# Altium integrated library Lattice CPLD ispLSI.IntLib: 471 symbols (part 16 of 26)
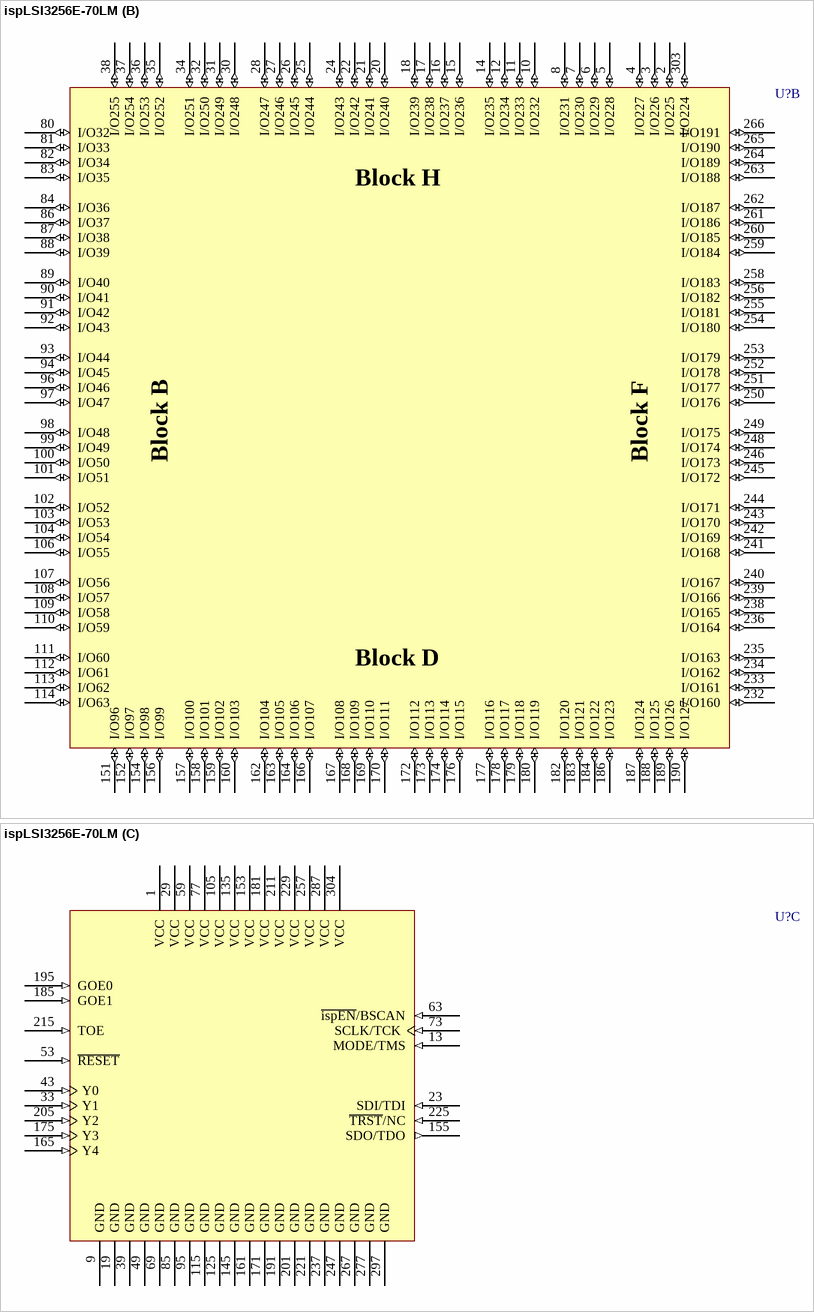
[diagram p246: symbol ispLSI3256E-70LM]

## ispLSI3256E-70LM
designator U?
In-System Programmable High-Density PLD
footprint MQFP304_N (Shrink QFP, 304-Leads, Body 40x40mm, Pitch 0.5mm, IPC Medium Density)
footprint MQFP304_L (Shrink QFP, 304-Leads, Body 40x40mm, Pitch 0.5mm, IPC High Density)
footprint MQFP304_M (Shrink QFP, 304-Leads, Body 40x40mm, Pitch 0.5mm, IPC Low Density)
3D model 3256E-MQFP304 (304-Pin Shrink Quad Flat Pack 0.5 mm Pitch)
part A pins: 40 I/O0 (io), 41 I/O1 (io), 42 I/O2 (io), 44 I/O3 (io), 45 I/O4 (io), 46 I/O5 (io), 47 I/O6 (io), 48 I/O7 (io), 50 I/O8 (io), 51 I/O9 (io), 52 I/O10 (io), 54 I/O11 (io), 55 I/O12 (io), 56 I/O13 (io), 57 I/O14 (io), 58 I/O15 (io), 60 I/O16 (io), 61 I/O17 (io), 62 I/O18 (io), 64 I/O19 (io), 65 I/O20 (io), 66 I/O21 (io), 67 I/O22 (io), 68 I/O23 (io), 70 I/O24 (io), 71 I/O25 (io), 72 I/O26 (io), 74 I/O27 (io), 75 I/O28 (io), 76 I/O29 (io), 78 I/O30 (io), 79 I/O31 (io), 116 I/O64 (io), 117 I/O65 (io), 118 I/O66 (io), 119 I/O67 (io), 120 I/O68 (io), 121 I/O69 (io), 122 I/O70 (io), 123 I/O71 (io), 124 I/O72 (io), 126 I/O73 (io), 127 I/O74 (io), 128 I/O75 (io), 129 I/O76 (io), 130 I/O77 (io), 131 I/O78 (io), 132 I/O79 (io), 133 I/O80 (io), 134 I/O81 (io), 136 I/O82 (io), 137 I/O83 (io), 138 I/O84 (io), 139 I/O85 (io), 140 I/O86 (io), 141 I/O87 (io), 142 I/O88 (io), 143 I/O89 (io), 144 I/O90 (io), 146 I/O91 (io), 147 I/O92 (io), 148 I/O93 (io), 149 I/O94 (io), 150 I/O95 (io), 192 I/O128 (io), 193 I/O129 (io), 194 I/O130 (io), 196 I/O131 (io), 197 I/O132 (io), 198 I/O133 (io), 199 I/O134 (io), 200 I/O135 (io), 202 I/O136 (io), 203 I/O137 (io), 204 I/O138 (io), 206 I/O139 (io), 207 I/O140 (io), 208 I/O141 (io), 209 I/O142 (io), 210 I/O143 (io), 212 I/O144 (io), 213 I/O145 (io), 214 I/O146 (io), 216 I/O147 (io), 217 I/O148 (io), 218 I/O149 (io), 219 I/O150 (io), 220 I/O151 (io), 222 I/O152 (io), 223 I/O153 (io), 224 I/O154 (io), 226 I/O155 (io), 227 I/O156 (io), 228 I/O157 (io), 230 I/O158 (io), 231 I/O159 (io), 268 I/O192 (io), 269 I/O193 (io), 270 I/O194 (io), 271 I/O195 (io), 272 I/O196 (io), 273 I/O197 (io), 274 I/O198 (io), 275 I/O199 (io), 276 I/O200 (io), 278 I/O201 (io), 279 I/O202 (io), 280 I/O203 (io), 281 I/O204 (io), 282 I/O205 (io), 283 I/O206 (io), 284 I/O207 (io), 285 I/O208 (io), 286 I/O209 (io), 288 I/O210 (io), 289 I/O211 (io), 290 I/O212 (io), 291 I/O213 (io), 292 I/O214 (io), 293 I/O215 (io), 294 I/O216 (io), 295 I/O217 (io), 296 I/O218 (io), 298 I/O219 (io), 299 I/O220 (io), 300 I/O221 (io), 301 I/O222 (io), 302 I/O223 (io)
part B pins: 2 I/O225 (io), 3 I/O226 (io), 4 I/O227 (io), 5 I/O228 (io), 6 I/O229 (io), 7 I/O230 (io), 8 I/O231 (io), 10 I/O232 (io), 11 I/O233 (io), 12 I/O234 (io), 14 I/O235 (io), 15 I/O236 (io), 16 I/O237 (io), 17 I/O238 (io), 18 I/O239 (io), 20 I/O240 (io), 21 I/O241 (io), 22 I/O242 (io), 24 I/O243 (io), 25 I/O244 (io), 26 I/O245 (io), 27 I/O246 (io), 28 I/O247 (io), 30 I/O248 (io), 31 I/O249 (io), 32 I/O250 (io), 34 I/O251 (io), 35 I/O252 (io), 36 I/O253 (io), 37 I/O254 (io), 38 I/O255 (io), 80 I/O32 (io), 81 I/O33 (io), 82 I/O34 (io), 83 I/O35 (io), 84 I/O36 (io), 86 I/O37 (io), 87 I/O38 (io), 88 I/O39 (io), 89 I/O40 (io), 90 I/O41 (io), 91 I/O42 (io), 92 I/O43 (io), 93 I/O44 (io), 94 I/O45 (io), 96 I/O46 (io), 97 I/O47 (io), 98 I/O48 (io), 99 I/O49 (io), 100 I/O50 (io), 101 I/O51 (io), 102 I/O52 (io), 103 I/O53 (io), 104 I/O54 (io), 106 I/O55 (io), 107 I/O56 (io), 108 I/O57 (io), 109 I/O58 (io), 110 I/O59 (io), 111 I/O60 (io), 112 I/O61 (io), 113 I/O62 (io), 114 I/O63 (io), 151 I/O96 (io), 152 I/O97 (io), 154 I/O98 (io), 156 I/O99 (io), 157 I/O100 (io), 158 I/O101 (io), 159 I/O102 (io), 160 I/O103 (io), 162 I/O104 (io), 163 I/O105 (io), 164 I/O106 (io), 166 I/O107 (io), 167 I/O108 (io), 168 I/O109 (io), 169 I/O110 (io), 170 I/O111 (io), 172 I/O112 (io), 173 I/O113 (io), 174 I/O114 (io), 176 I/O115 (io), 177 I/O116 (io), 178 I/O117 (io), 179 I/O118 (io), 180 I/O119 (io), 182 I/O120 (io), 183 I/O121 (io), 184 I/O122 (io), 186 I/O123 (io), 187 I/O124 (io), 188 I/O125 (io), 189 I/O126 (io), 190 I/O127 (io), 232 I/O160 (io), 233 I/O161 (io), 234 I/O162 (io), 235 I/O163 (io), 236 I/O164 (io), 238 I/O165 (io), 239 I/O166 (io), 240 I/O167 (io), 241 I/O168 (io), 242 I/O169 (io), 243 I/O170 (io), 244 I/O171 (io), 245 I/O172 (io), 246 I/O173 (io), 248 I/O174 (io), 249 I/O175 (io), 250 I/O176 (io), 251 I/O177 (io), 252 I/O178 (io), 253 I/O179 (io), 254 I/O180 (io), 255 I/O181 (io), 256 I/O182 (io), 258 I/O183 (io), 259 I/O184 (io), 260 I/O185 (io), 261 I/O186 (io), 262 I/O187 (io), 263 I/O188 (io), 264 I/O189 (io), 265 I/O190 (io), 266 I/O191 (io), 303 I/O224 (io)
part C pins: 1 VCC (power), 9 GND (power), 13 MODE/TMS (in), 19 GND (power), 23 SDI/TDI (in), 29 VCC (power), 33 Y1 (in), 39 GND (power), 43 Y0 (in), 49 GND (power), 53 ~{RESET} (in), 59 VCC (power), 63 ~{ispEN}/BSCAN (in), 69 GND (power), 73 SCLK/TCK (in), 77 VCC (power), 85 GND (power), 95 GND (power), 105 VCC (power), 115 GND (power), 125 GND (power), 135 VCC (power), 145 GND (power), 153 VCC (power), 155 SDO/TDO (out), 161 GND (power), 165 Y4 (in), 171 GND (power), 175 Y3 (in), 181 VCC (power), 185 GOE1 (in), 191 GND (power), 195 GOE0 (in), 201 GND (power), 205 Y2 (in), 211 VCC (power), 215 TOE (in), 221 GND (power), 225 ~{TRST}/NC (in), 229 VCC (power), 237 GND (power), 247 GND (power), 257 VCC (power), 267 GND (power), 277 GND (power), 287 VCC (power), 297 GND (power), 304 VCC (power)

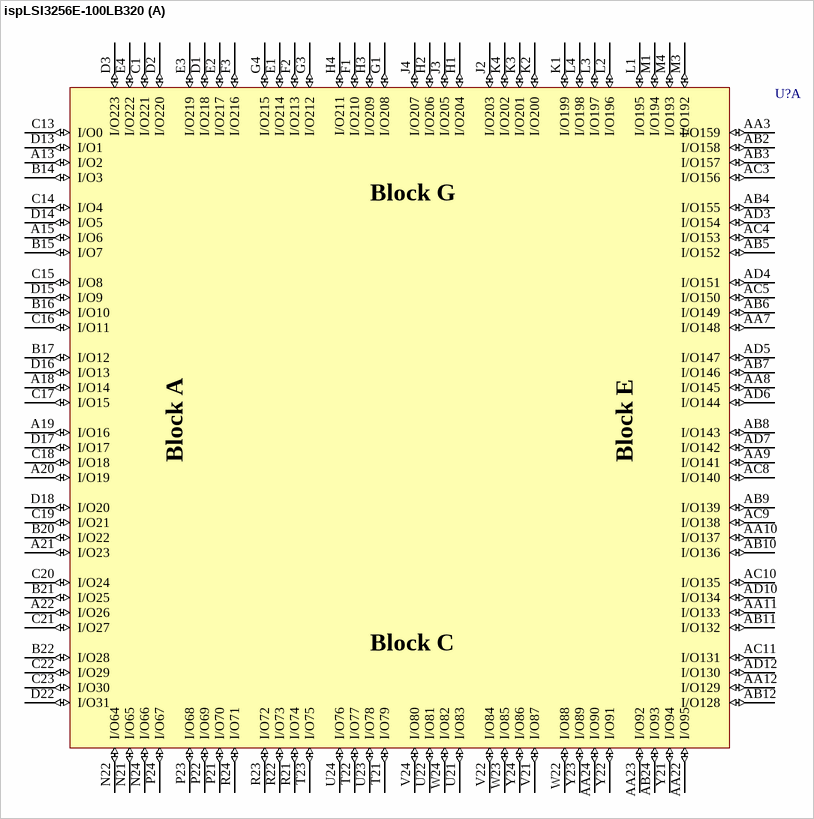
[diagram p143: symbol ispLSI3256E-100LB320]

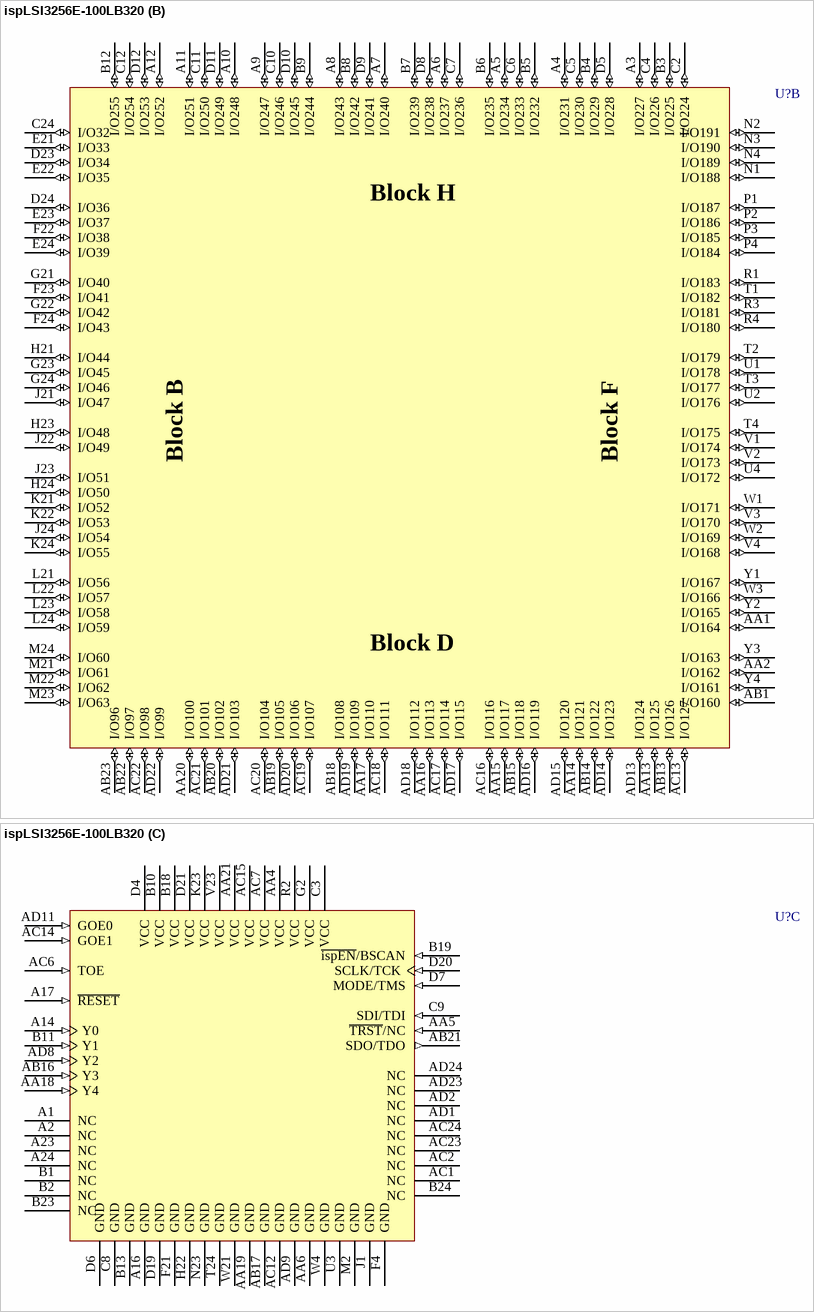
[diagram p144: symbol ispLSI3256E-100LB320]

## ispLSI3256E-100LB320
designator U?
In-System Programmable High-Density PLD
footprint SBGA320 (BGA, 320-Leads, Body 31x31mm, Pitch 1.27mm)
3D model 3256E-SBGA320 (320-Ball Super Ball Grid Array (SBGA320))
part A pins: A13 I/O2 (io), A15 I/O6 (io), A18 I/O14 (io), A19 I/O16 (io), A20 I/O19 (io), A21 I/O23 (io), A22 I/O26 (io), AA3 I/O159 (io), AA7 I/O148 (io), AA8 I/O145 (io), AA9 I/O141 (io), AA10 I/O137 (io), AA11 I/O133 (io), AA12 I/O129 (io), AA22 I/O95 (io), AA23 I/O92 (io), AA24 I/O90 (io), AB2 I/O158 (io), AB3 I/O157 (io), AB4 I/O155 (io), AB5 I/O152 (io), AB6 I/O149 (io), AB7 I/O146 (io), AB8 I/O143 (io), AB9 I/O139 (io), AB10 I/O136 (io), AB11 I/O132 (io), AB12 I/O128 (io), AB24 I/O93 (io), AC3 I/O156 (io), AC4 I/O153 (io), AC5 I/O150 (io), AC8 I/O140 (io), AC9 I/O138 (io), AC10 I/O135 (io), AC11 I/O131 (io), AD3 I/O154 (io), AD4 I/O151 (io), AD5 I/O147 (io), AD6 I/O144 (io), AD7 I/O142 (io), AD10 I/O134 (io), AD12 I/O130 (io), B14 I/O3 (io), B15 I/O7 (io), B16 I/O10 (io), B17 I/O12 (io), B20 I/O22 (io), B21 I/O25 (io), B22 I/O28 (io), C1 I/O221 (io), C13 I/O0 (io), C14 I/O4 (io), C15 I/O8 (io), C16 I/O11 (io), C17 I/O15 (io), C18 I/O18 (io), C19 I/O21 (io), C20 I/O24 (io), C21 I/O27 (io), C22 I/O29 (io), C23 I/O30 (io), D1 I/O218 (io), D2 I/O220 (io), D3 I/O223 (io), D13 I/O1 (io), D14 I/O5 (io), D15 I/O9 (io), D16 I/O13 (io), D17 I/O17 (io), D18 I/O20 (io), D22 I/O31 (io), E1 I/O214 (io), E2 I/O217 (io), E3 I/O219 (io), E4 I/O222 (io), F1 I/O210 (io), F2 I/O213 (io), F3 I/O216 (io), G1 I/O208 (io), G3 I/O212 (io), G4 I/O215 (io), H1 I/O204 (io), H2 I/O206 (io), H3 I/O209 (io), H4 I/O211 (io), J2 I/O203 (io), J3 I/O205 (io), J4 I/O207 (io), K1 I/O199 (io), K2 I/O200 (io), K3 I/O201 (io), K4 I/O202 (io), L1 I/O195 (io), L2 I/O196 (io), L3 I/O197 (io), L4 I/O198 (io), M1 I/O194 (io), M3 I/O192 (io), M4 I/O193 (io), N21 I/O65 (io), N22 I/O64 (io), N24 I/O66 (io), P21 I/O70 (io), P22 I/O69 (io), P23 I/O68 (io), P24 I/O67 (io), R21 I/O74 (io), R22 I/O73 (io), R23 I/O72 (io), R24 I/O71 (io), T21 I/O79 (io), T22 I/O77 (io), T23 I/O75 (io), U21 I/O83 (io), U22 I/O81 (io), U23 I/O78 (io), U24 I/O76 (io), V21 I/O87 (io), V22 I/O84 (io), V24 I/O80 (io), W22 I/O88 (io), W23 I/O85 (io), W24 I/O82 (io), Y21 I/O94 (io), Y22 I/O91 (io), Y23 I/O89 (io), Y24 I/O86 (io)
part B pins: A3 I/O227 (io), A4 I/O231 (io), A5 I/O234 (io), A6 I/O237 (io), A7 I/O240 (io), A8 I/O243 (io), A9 I/O247 (io), A10 I/O248 (io), A11 I/O251 (io), A12 I/O252 (io), AA1 I/O164 (io), AA2 I/O162 (io), AA13 I/O125 (io), AA14 I/O121 (io), AA15 I/O117 (io), AA16 I/O113 (io), AA17 I/O110 (io), AA20 I/O100 (io), AB1 I/O160 (io), AB13 I/O126 (io), AB14 I/O122 (io), AB15 I/O118 (io), AB18 I/O108 (io), AB19 I/O105 (io), AB20 I/O102 (io), AB22 I/O97 (io), AB23 I/O96 (io), AC13 I/O127 (io), AC16 I/O116 (io), AC17 I/O114 (io), AC18 I/O111 (io), AC19 I/O107 (io), AC20 I/O104 (io), AC21 I/O101 (io), AC22 I/O98 (io), AD13 I/O124 (io), AD14 I/O123 (io), AD15 I/O120 (io), AD16 I/O119 (io), AD17 I/O115 (io), AD18 I/O112 (io), AD19 I/O109 (io), AD20 I/O106 (io), AD21 I/O103 (io), AD22 I/O99 (io), B3 I/O225 (io), B4 I/O229 (io), B5 I/O232 (io), B6 I/O235 (io), B7 I/O239 (io), B8 I/O242 (io), B9 I/O244 (io), B12 I/O255 (io), C2 I/O224 (io), C4 I/O226 (io), C5 I/O230 (io), C6 I/O233 (io), C7 I/O236 (io), C10 I/O246 (io), C11 I/O250 (io), C12 I/O254 (io), C24 I/O32 (io), D5 I/O228 (io), D8 I/O238 (io), D9 I/O241 (io), D10 I/O245 (io), D11 I/O249 (io), D12 I/O253 (io), D23 I/O34 (io), D24 I/O36 (io), E21 I/O33 (io), E22 I/O35 (io), E23 I/O37 (io), E24 I/O39 (io), F22 I/O38 (io), F23 I/O41 (io), F24 I/O43 (io), G21 I/O40 (io), G22 I/O42 (io), G23 I/O45 (io), G24 I/O46 (io), H21 I/O44 (io), H23 I/O48 (io), H24 I/O50 (io), J21 I/O47 (io), J22 I/O49 (io), J23 I/O51 (io), J24 I/O54 (io), K21 I/O52 (io), K22 I/O53 (io), K24 I/O55 (io), L21 I/O56 (io), L22 I/O57 (io), L23 I/O58 (io), L24 I/O59 (io), M21 I/O61 (io), M22 I/O62 (io), M23 I/O63 (io), M24 I/O60 (io), N1 I/O188 (io), N2 I/O191 (io), N3 I/O190 (io), N4 I/O189 (io), P1 I/O187 (io), P2 I/O186 (io), P3 I/O185 (io), P4 I/O184 (io), R1 I/O183 (io), R3 I/O181 (io), R4 I/O180 (io), T1 I/O182 (io), T2 I/O179 (io), T3 I/O177 (io), T4 I/O175 (io), U1 I/O178 (io), U2 I/O176 (io), U4 I/O172 (io), V1 I/O174 (io), V2 I/O173 (io), V3 I/O170 (io), V4 I/O168 (io), W1 I/O171 (io), W2 I/O169 (io), W3 I/O166 (io), Y1 I/O167 (io), Y2 I/O165 (io), Y3 I/O163 (io), Y4 I/O161 (io)
part C pins: A1 NC, A2 NC, A14 Y0 (in), A16 GND (power), A17 ~{RESET} (in), A23 NC, A24 NC, AA4 VCC (power), AA5 ~{TRST}/NC (in), AA6 GND (power), AA18 Y4 (in), AA19 GND (power), AA21 VCC (power), AB16 Y3 (in), AB17 GND (power), AB21 SDO/TDO (out), AC1 NC, AC2 NC, AC6 TOE (in), AC7 VCC (power), AC12 GND (power), AC14 GOE1 (in), AC15 VCC (power), AC23 NC, AC24 NC, AD1 NC, AD2 NC, AD8 Y2 (in), AD9 GND (power), AD11 GOE0 (in), AD23 NC, AD24 NC, B1 NC, B2 NC, B10 VCC (power), B11 Y1 (in), B13 GND (power), B18 VCC (power), B19 ~{ispEN}/BSCAN (in), B23 NC, B24 NC, C3 VCC (power), C8 GND (power), C9 SDI/TDI (in), D4 VCC (power), D6 GND (power), D7 MODE/TMS (in), D19 GND (power), D20 SCLK/TCK (in), D21 VCC (power), F4 GND (power), F21 GND (power), G2 VCC (power), H22 GND (power), J1 GND (power), K23 VCC (power), M2 GND (power), N23 GND (power), R2 VCC (power), T24 GND (power), U3 GND (power), V23 VCC (power), W4 GND (power), W21 GND (power)

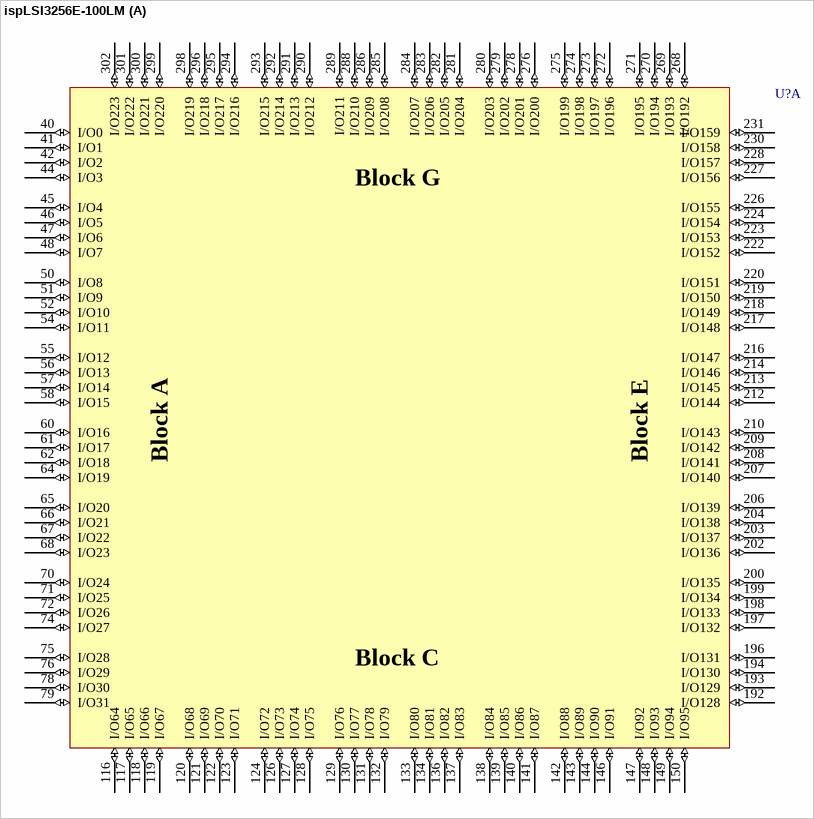
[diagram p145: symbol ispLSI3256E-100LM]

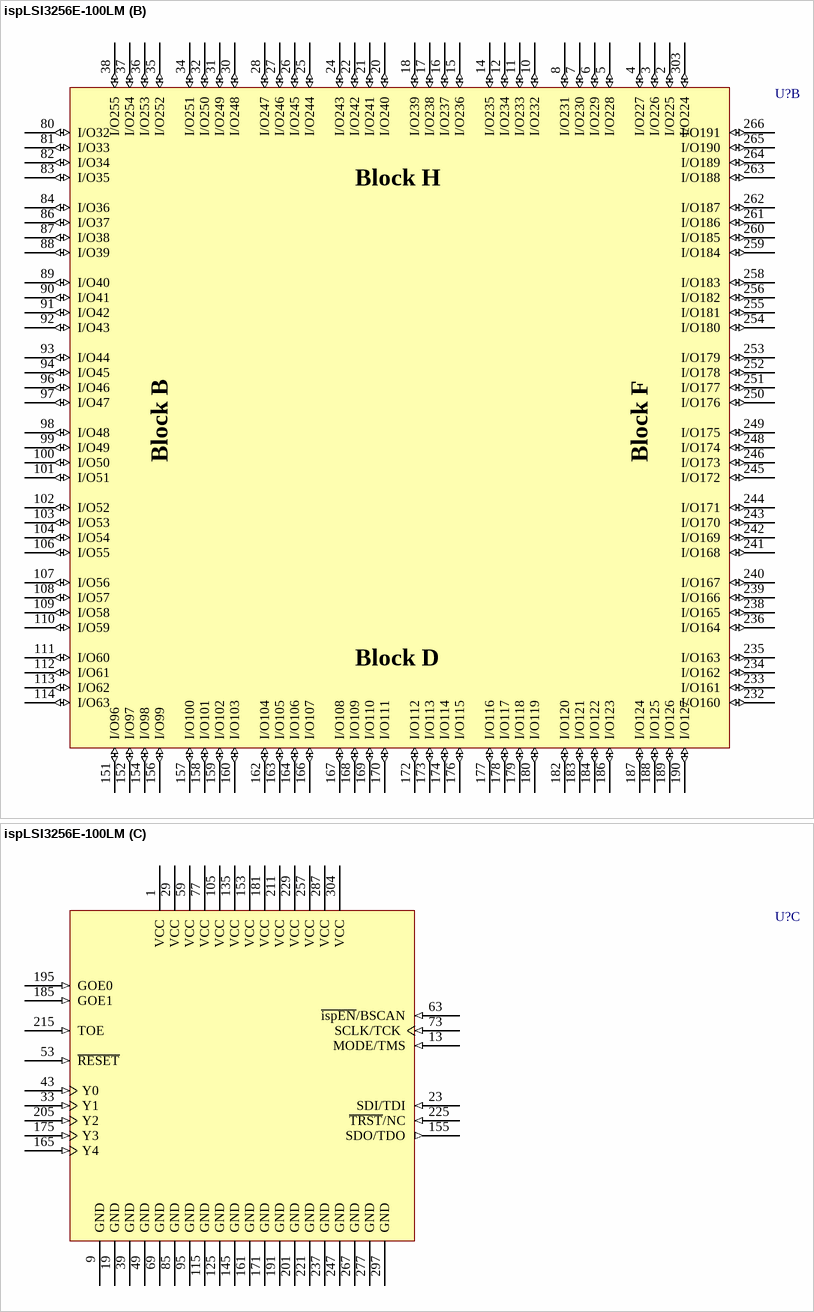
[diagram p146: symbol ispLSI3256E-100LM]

## ispLSI3256E-100LM
designator U?
In-System Programmable High-Density PLD
footprint MQFP304_N (Shrink QFP, 304-Leads, Body 40x40mm, Pitch 0.5mm, IPC Medium Density)
footprint MQFP304_L (Shrink QFP, 304-Leads, Body 40x40mm, Pitch 0.5mm, IPC High Density)
footprint MQFP304_M (Shrink QFP, 304-Leads, Body 40x40mm, Pitch 0.5mm, IPC Low Density)
3D model 3256E-MQFP304 (304-Pin Shrink Quad Flat Pack 0.5 mm Pitch)
part A pins: 40 I/O0 (io), 41 I/O1 (io), 42 I/O2 (io), 44 I/O3 (io), 45 I/O4 (io), 46 I/O5 (io), 47 I/O6 (io), 48 I/O7 (io), 50 I/O8 (io), 51 I/O9 (io), 52 I/O10 (io), 54 I/O11 (io), 55 I/O12 (io), 56 I/O13 (io), 57 I/O14 (io), 58 I/O15 (io), 60 I/O16 (io), 61 I/O17 (io), 62 I/O18 (io), 64 I/O19 (io), 65 I/O20 (io), 66 I/O21 (io), 67 I/O22 (io), 68 I/O23 (io), 70 I/O24 (io), 71 I/O25 (io), 72 I/O26 (io), 74 I/O27 (io), 75 I/O28 (io), 76 I/O29 (io), 78 I/O30 (io), 79 I/O31 (io), 116 I/O64 (io), 117 I/O65 (io), 118 I/O66 (io), 119 I/O67 (io), 120 I/O68 (io), 121 I/O69 (io), 122 I/O70 (io), 123 I/O71 (io), 124 I/O72 (io), 126 I/O73 (io), 127 I/O74 (io), 128 I/O75 (io), 129 I/O76 (io), 130 I/O77 (io), 131 I/O78 (io), 132 I/O79 (io), 133 I/O80 (io), 134 I/O81 (io), 136 I/O82 (io), 137 I/O83 (io), 138 I/O84 (io), 139 I/O85 (io), 140 I/O86 (io), 141 I/O87 (io), 142 I/O88 (io), 143 I/O89 (io), 144 I/O90 (io), 146 I/O91 (io), 147 I/O92 (io), 148 I/O93 (io), 149 I/O94 (io), 150 I/O95 (io), 192 I/O128 (io), 193 I/O129 (io), 194 I/O130 (io), 196 I/O131 (io), 197 I/O132 (io), 198 I/O133 (io), 199 I/O134 (io), 200 I/O135 (io), 202 I/O136 (io), 203 I/O137 (io), 204 I/O138 (io), 206 I/O139 (io), 207 I/O140 (io), 208 I/O141 (io), 209 I/O142 (io), 210 I/O143 (io), 212 I/O144 (io), 213 I/O145 (io), 214 I/O146 (io), 216 I/O147 (io), 217 I/O148 (io), 218 I/O149 (io), 219 I/O150 (io), 220 I/O151 (io), 222 I/O152 (io), 223 I/O153 (io), 224 I/O154 (io), 226 I/O155 (io), 227 I/O156 (io), 228 I/O157 (io), 230 I/O158 (io), 231 I/O159 (io), 268 I/O192 (io), 269 I/O193 (io), 270 I/O194 (io), 271 I/O195 (io), 272 I/O196 (io), 273 I/O197 (io), 274 I/O198 (io), 275 I/O199 (io), 276 I/O200 (io), 278 I/O201 (io), 279 I/O202 (io), 280 I/O203 (io), 281 I/O204 (io), 282 I/O205 (io), 283 I/O206 (io), 284 I/O207 (io), 285 I/O208 (io), 286 I/O209 (io), 288 I/O210 (io), 289 I/O211 (io), 290 I/O212 (io), 291 I/O213 (io), 292 I/O214 (io), 293 I/O215 (io), 294 I/O216 (io), 295 I/O217 (io), 296 I/O218 (io), 298 I/O219 (io), 299 I/O220 (io), 300 I/O221 (io), 301 I/O222 (io), 302 I/O223 (io)
part B pins: 2 I/O225 (io), 3 I/O226 (io), 4 I/O227 (io), 5 I/O228 (io), 6 I/O229 (io), 7 I/O230 (io), 8 I/O231 (io), 10 I/O232 (io), 11 I/O233 (io), 12 I/O234 (io), 14 I/O235 (io), 15 I/O236 (io), 16 I/O237 (io), 17 I/O238 (io), 18 I/O239 (io), 20 I/O240 (io), 21 I/O241 (io), 22 I/O242 (io), 24 I/O243 (io), 25 I/O244 (io), 26 I/O245 (io), 27 I/O246 (io), 28 I/O247 (io), 30 I/O248 (io), 31 I/O249 (io), 32 I/O250 (io), 34 I/O251 (io), 35 I/O252 (io), 36 I/O253 (io), 37 I/O254 (io), 38 I/O255 (io), 80 I/O32 (io), 81 I/O33 (io), 82 I/O34 (io), 83 I/O35 (io), 84 I/O36 (io), 86 I/O37 (io), 87 I/O38 (io), 88 I/O39 (io), 89 I/O40 (io), 90 I/O41 (io), 91 I/O42 (io), 92 I/O43 (io), 93 I/O44 (io), 94 I/O45 (io), 96 I/O46 (io), 97 I/O47 (io), 98 I/O48 (io), 99 I/O49 (io), 100 I/O50 (io), 101 I/O51 (io), 102 I/O52 (io), 103 I/O53 (io), 104 I/O54 (io), 106 I/O55 (io), 107 I/O56 (io), 108 I/O57 (io), 109 I/O58 (io), 110 I/O59 (io), 111 I/O60 (io), 112 I/O61 (io), 113 I/O62 (io), 114 I/O63 (io), 151 I/O96 (io), 152 I/O97 (io), 154 I/O98 (io), 156 I/O99 (io), 157 I/O100 (io), 158 I/O101 (io), 159 I/O102 (io), 160 I/O103 (io), 162 I/O104 (io), 163 I/O105 (io), 164 I/O106 (io), 166 I/O107 (io), 167 I/O108 (io), 168 I/O109 (io), 169 I/O110 (io), 170 I/O111 (io), 172 I/O112 (io), 173 I/O113 (io), 174 I/O114 (io), 176 I/O115 (io), 177 I/O116 (io), 178 I/O117 (io), 179 I/O118 (io), 180 I/O119 (io), 182 I/O120 (io), 183 I/O121 (io), 184 I/O122 (io), 186 I/O123 (io), 187 I/O124 (io), 188 I/O125 (io), 189 I/O126 (io), 190 I/O127 (io), 232 I/O160 (io), 233 I/O161 (io), 234 I/O162 (io), 235 I/O163 (io), 236 I/O164 (io), 238 I/O165 (io), 239 I/O166 (io), 240 I/O167 (io), 241 I/O168 (io), 242 I/O169 (io), 243 I/O170 (io), 244 I/O171 (io), 245 I/O172 (io), 246 I/O173 (io), 248 I/O174 (io), 249 I/O175 (io), 250 I/O176 (io), 251 I/O177 (io), 252 I/O178 (io), 253 I/O179 (io), 254 I/O180 (io), 255 I/O181 (io), 256 I/O182 (io), 258 I/O183 (io), 259 I/O184 (io), 260 I/O185 (io), 261 I/O186 (io), 262 I/O187 (io), 263 I/O188 (io), 264 I/O189 (io), 265 I/O190 (io), 266 I/O191 (io), 303 I/O224 (io)
part C pins: 1 VCC (power), 9 GND (power), 13 MODE/TMS (in), 19 GND (power), 23 SDI/TDI (in), 29 VCC (power), 33 Y1 (in), 39 GND (power), 43 Y0 (in), 49 GND (power), 53 ~{RESET} (in), 59 VCC (power), 63 ~{ispEN}/BSCAN (in), 69 GND (power), 73 SCLK/TCK (in), 77 VCC (power), 85 GND (power), 95 GND (power), 105 VCC (power), 115 GND (power), 125 GND (power), 135 VCC (power), 145 GND (power), 153 VCC (power), 155 SDO/TDO (out), 161 GND (power), 165 Y4 (in), 171 GND (power), 175 Y3 (in), 181 VCC (power), 185 GOE1 (in), 191 GND (power), 195 GOE0 (in), 201 GND (power), 205 Y2 (in), 211 VCC (power), 215 TOE (in), 221 GND (power), 225 ~{TRST}/NC (in), 229 VCC (power), 237 GND (power), 247 GND (power), 257 VCC (power), 267 GND (power), 277 GND (power), 287 VCC (power), 297 GND (power), 304 VCC (power)

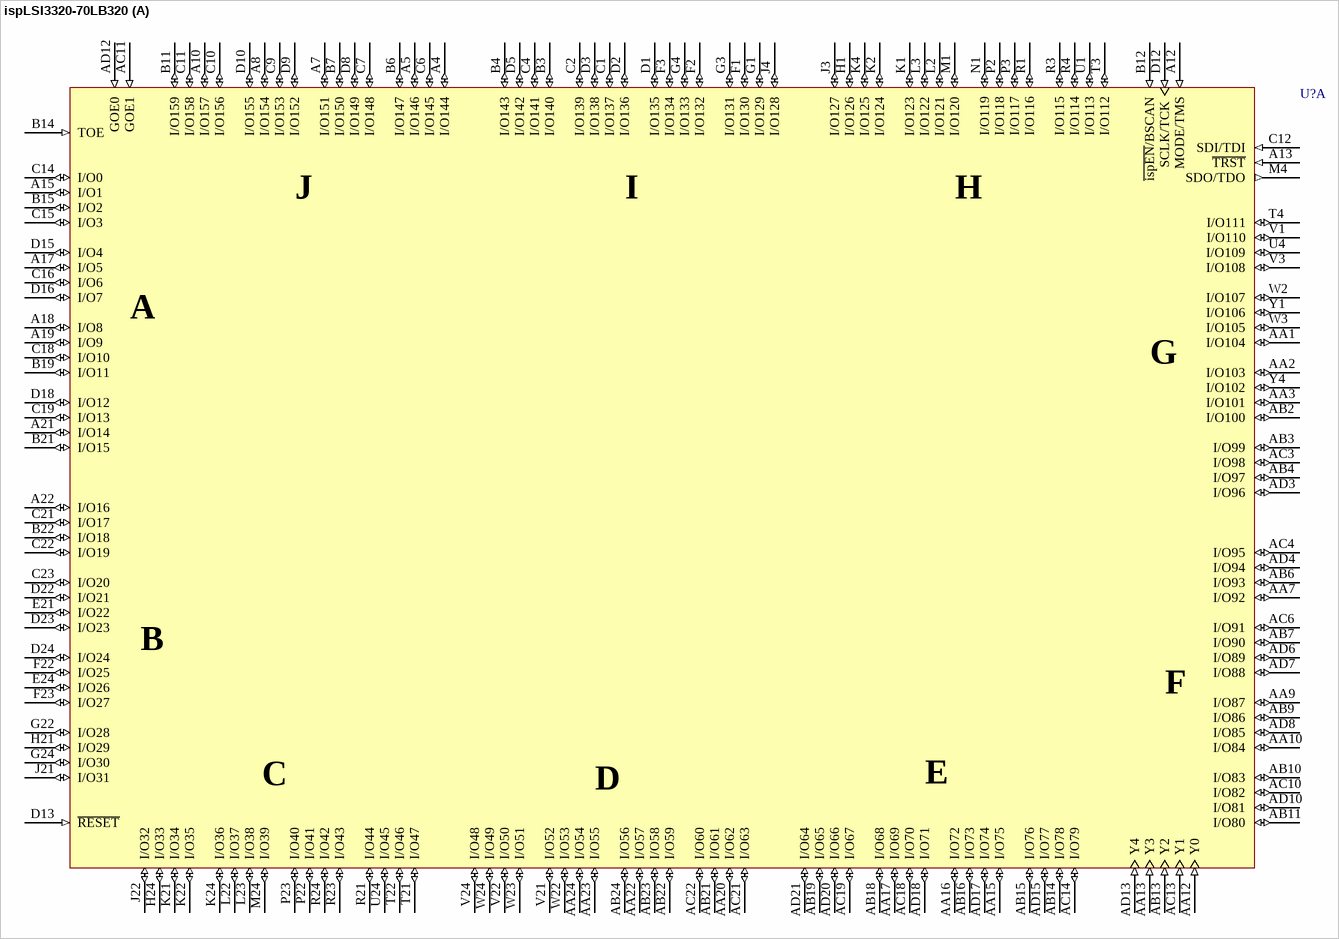
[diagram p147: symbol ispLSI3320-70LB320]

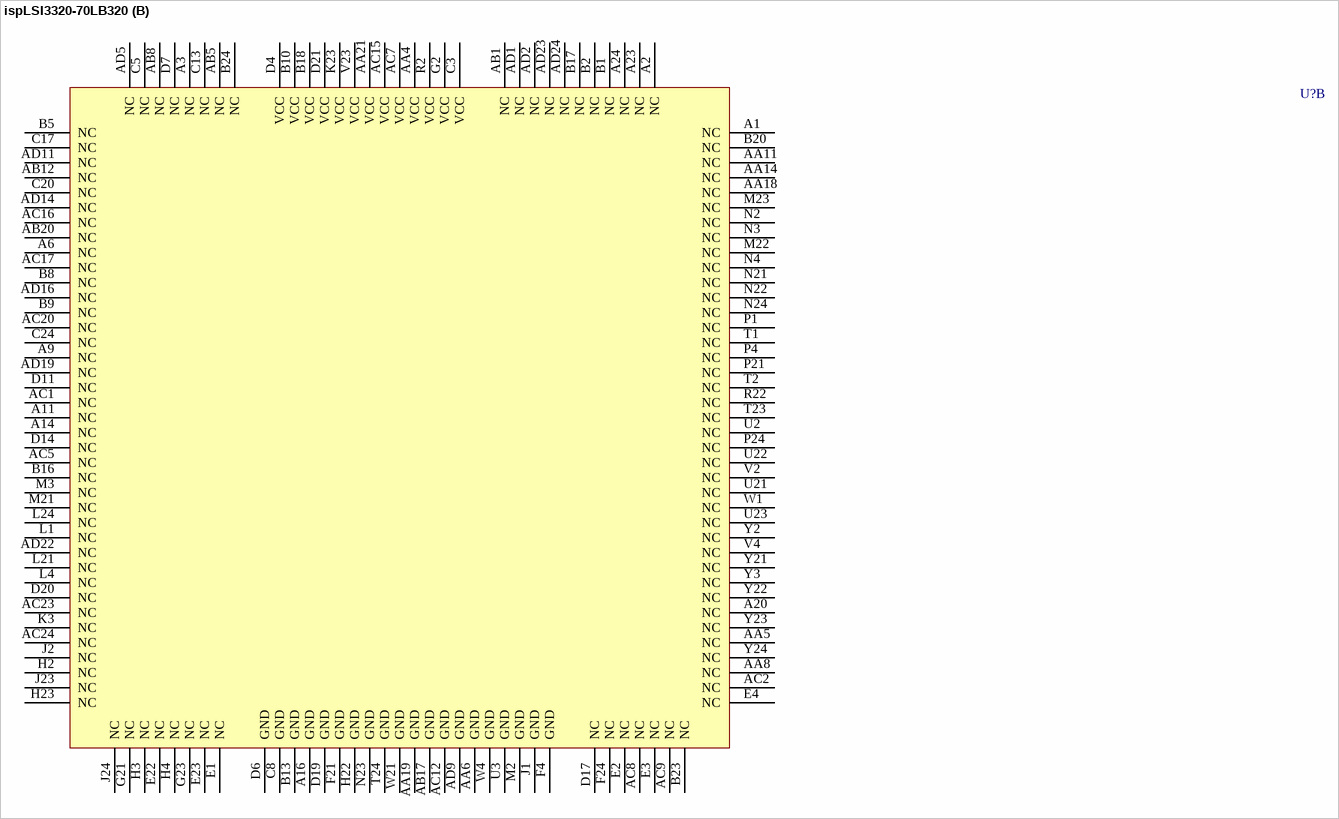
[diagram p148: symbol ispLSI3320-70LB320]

## ispLSI3320-70LB320
designator U?
In-System Programmable High-Density PLD
footprint SBGA320 (BGA, 320-Leads, Body 31x31mm, Pitch 1.27mm)
3D model 3320-SBGA320 (320-Ball Super Ball Grid Array (SBGA320))
part A pins: A4 I/O144 (io), A5 I/O146 (io), A7 I/O151 (io), A8 I/O154 (io), A10 I/O157 (io), A12 MODE/TMS (in), A13 ~{TRST} (in), A15 I/O1 (io), A17 I/O5 (io), A18 I/O8 (io), A19 I/O9 (io), A21 I/O14 (io), A22 I/O16 (io), AA1 I/O104 (io), AA2 I/O103 (io), AA3 I/O101 (io), AA7 I/O92 (io), AA9 I/O87 (io), AA10 I/O84 (io), AA12 Y0 (in), AA13 Y3 (in), AA15 I/O75 (io), AA16 I/O72 (io), AA17 I/O69 (io), AA20 I/O62 (io), AA22 I/O57 (io), AA23 I/O55 (io), AA24 I/O54 (io), AB2 I/O100 (io), AB3 I/O99 (io), AB4 I/O97 (io), AB6 I/O93 (io), AB7 I/O90 (io), AB9 I/O86 (io), AB10 I/O83 (io), AB11 I/O80 (io), AB13 Y2 (in), AB14 I/O78 (io), AB15 I/O76 (io), AB16 I/O73 (io), AB18 I/O68 (io), AB19 I/O65 (io), AB21 I/O61 (io), AB22 I/O59 (io), AB23 I/O58 (io), AB24 I/O56 (io), AC3 I/O98 (io), AC4 I/O95 (io), AC6 I/O91 (io), AC10 I/O82 (io), AC11 GOE1 (in), AC13 Y1 (in), AC14 I/O79 (io), AC18 I/O70 (io), AC19 I/O67 (io), AC21 I/O63 (io), AC22 I/O60 (io), AD3 I/O96 (io), AD4 I/O94 (io), AD6 I/O89 (io), AD7 I/O88 (io), AD8 I/O85 (io), AD10 I/O81 (io), AD12 GOE0 (in), AD13 Y4 (in), AD15 I/O77 (io), AD17 I/O74 (io), AD18 I/O71 (io), AD20 I/O66 (io), AD21 I/O64 (io), B3 I/O140 (io), B4 I/O143 (io), B6 I/O147 (io), B7 I/O150 (io), B11 I/O159 (io), B12 ~{ispEN}/BSCAN (in), B14 TOE (in), B15 I/O2 (io), B19 I/O11 (io), B21 I/O15 (io), B22 I/O18 (io), C1 I/O137 (io), C2 I/O139 (io), C4 I/O141 (io), C6 I/O145 (io), C7 I/O148 (io), C9 I/O153 (io), C10 I/O156 (io), C11 I/O158 (io), C12 SDI/TDI (in), C14 I/O0 (io), C15 I/O3 (io), C16 I/O6 (io), C18 I/O10 (io), C19 I/O13 (io), C21 I/O17 (io), C22 I/O19 (io), C23 I/O20 (io), D1 I/O135 (io), D2 I/O136 (io), D3 I/O138 (io), D5 I/O142 (io), D8 I/O149 (io), D9 I/O152 (io), D10 I/O155 (io), D12 SCLK/TCK (in), D13 ~{RESET} (in), D15 I/O4 (io), D16 I/O7 (io), D18 I/O12 (io), D22 I/O21 (io), D23 I/O23 (io), D24 I/O24 (io), E21 I/O22 (io), E24 I/O26 (io), F1 I/O130 (io), F2 I/O132 (io), F3 I/O134 (io), F22 I/O25 (io), F23 I/O27 (io), G1 I/O129 (io), G3 I/O131 (io), G4 I/O133 (io), G22 I/O28 (io), G24 I/O30 (io), H1 I/O126 (io), H21 I/O29 (io), H24 I/O33 (io), J3 I/O127 (io), J4 I/O128 (io), J21 I/O31 (io), J22 I/O32 (io), K1 I/O123 (io), K2 I/O124 (io), K4 I/O125 (io), K21 I/O34 (io), K22 I/O35 (io), K24 I/O36 (io), L2 I/O121 (io), L3 I/O122 (io), L22 I/O37 (io), L23 I/O38 (io), M1 I/O120 (io), M4 SDO/TDO (out), M24 I/O39 (io), N1 I/O119 (io), P2 I/O118 (io), P3 I/O117 (io), P22 I/O41 (io), P23 I/O40 (io), R1 I/O116 (io), R3 I/O115 (io), R4 I/O114 (io), R21 I/O44 (io), R23 I/O43 (io), R24 I/O42 (io), T3 I/O112 (io), T4 I/O111 (io), T21 I/O47 (io), T22 I/O46 (io), U1 I/O113 (io), U4 I/O109 (io), U24 I/O45 (io), V1 I/O110 (io), V3 I/O108 (io), V21 I/O52 (io), V22 I/O50 (io), V24 I/O48 (io), W2 I/O107 (io), W3 I/O105 (io), W22 I/O53 (io), W23 I/O51 (io), W24 I/O49 (io), Y1 I/O106 (io), Y4 I/O102 (io)
part B pins: A1 NC, A2 NC, A3 NC, A6 NC, A9 NC, A11 NC, A14 NC, A16 GND (power), A20 NC, A23 NC, A24 NC, AA4 VCC (power), AA5 NC, AA6 GND (power), AA8 NC, AA11 NC, AA14 NC, AA18 NC, AA19 GND (power), AA21 VCC (power), AB1 NC, AB5 NC, AB8 NC, AB12 NC, AB17 GND (power), AB20 NC, AC1 NC, AC2 NC, AC5 NC, AC7 VCC (power), AC8 NC, AC9 NC, AC12 GND (power), AC15 VCC (power), AC16 NC, AC17 NC, AC20 NC, AC23 NC, AC24 NC, AD1 NC, AD2 NC, AD5 NC, AD9 GND (power), AD11 NC, AD14 NC, AD16 NC, AD19 NC, AD22 NC, AD23 NC, AD24 NC, B1 NC, B2 NC, B5 NC, B8 NC, B9 NC, B10 VCC (power), B13 GND (power), B16 NC, B17 NC, B18 VCC (power), B20 NC, B23 NC, B24 NC, C3 VCC (power), C5 NC, C8 GND (power), C13 NC, C17 NC, C20 NC, C24 NC, D4 VCC (power), D6 GND (power), D7 NC, D11 NC, D14 NC, D17 NC, D19 GND (power), D20 NC, D21 VCC (power), E1 NC, E2 NC, E3 NC, E4 NC, E22 NC, E23 NC, F4 GND (power), F21 GND (power), F24 NC, G2 VCC (power), G21 NC, G23 NC, H2 NC, H3 NC, H4 NC, H22 GND (power), H23 NC, J1 GND (power), J2 NC, J23 NC, J24 NC, K3 NC, K23 VCC (power), L1 NC, L4 NC, L21 NC, L24 NC, M2 GND (power), M3 NC, M21 NC, M22 NC, M23 NC, N2 NC, N3 NC, N4 NC, N21 NC, N22 NC, N23 GND (power), N24 NC, P1 NC, P4 NC, P21 NC, P24 NC, R2 VCC (power), R22 NC, T1 NC, T2 NC, T23 NC, T24 GND (power), U2 NC, U3 GND (power), U21 NC, U22 NC, U23 NC, V2 NC, V4 NC, V23 VCC (power), W1 NC, W4 GND (power), W21 GND (power), Y2 NC, Y3 NC, Y21 NC, Y22 NC, Y23 NC, Y24 NC

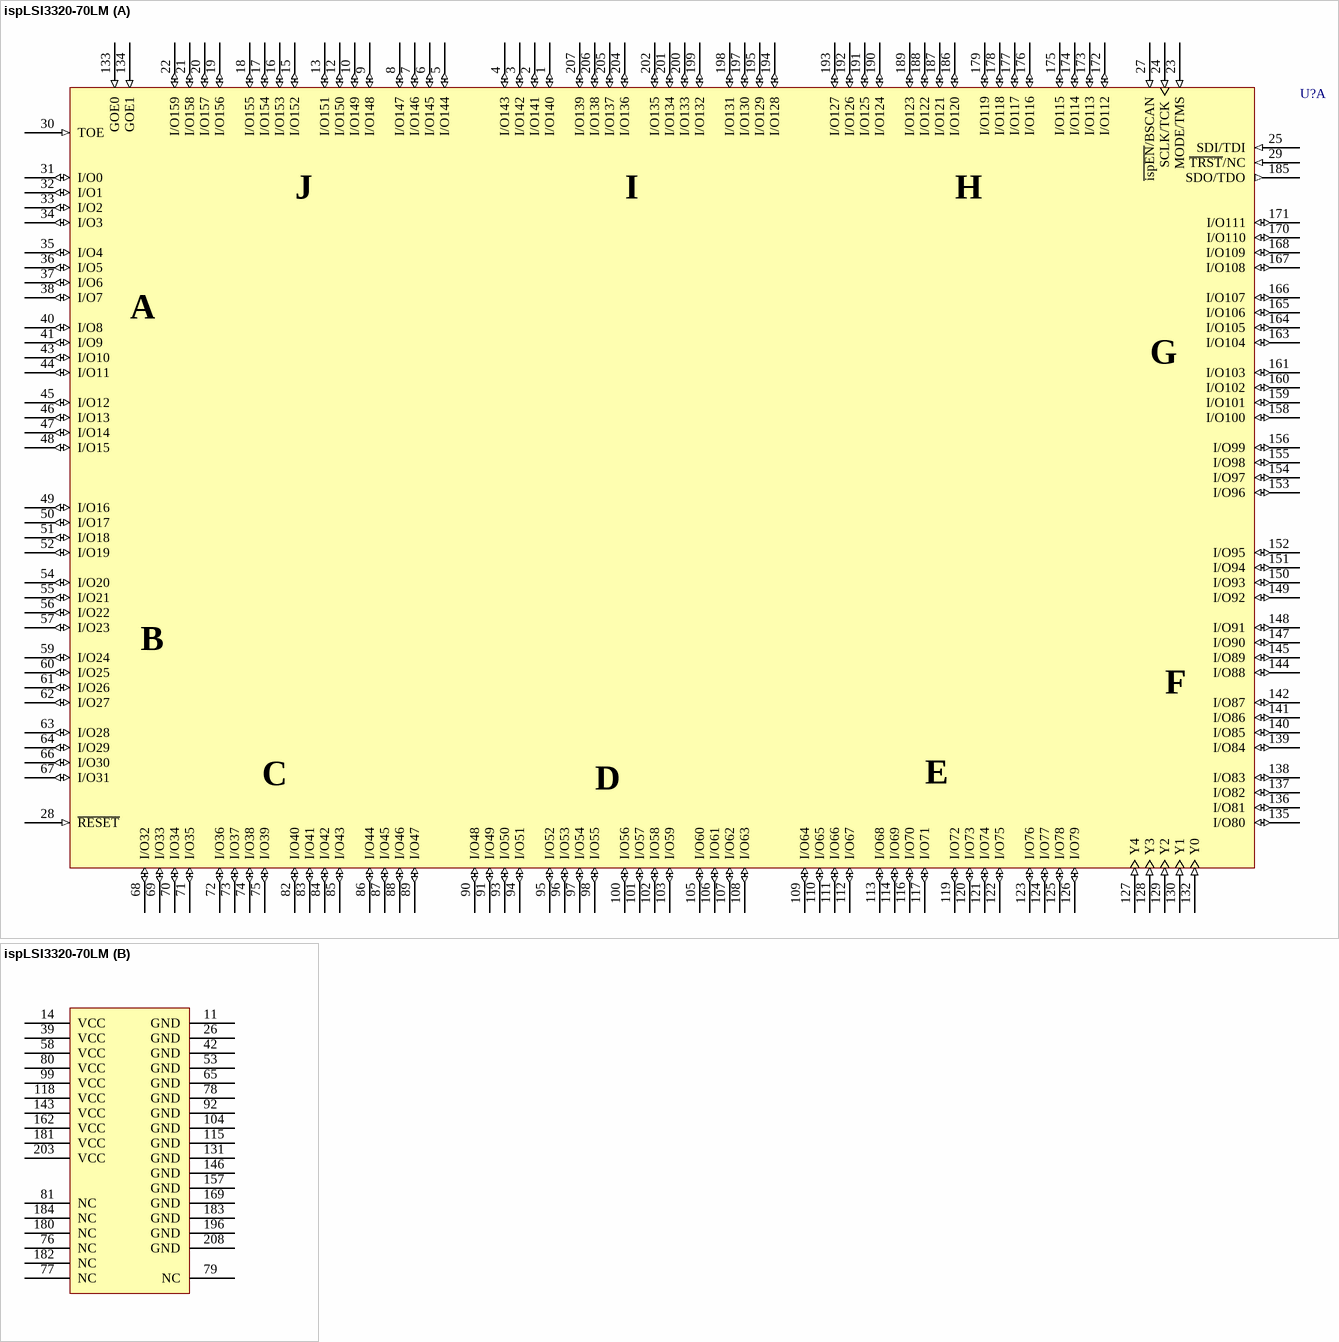
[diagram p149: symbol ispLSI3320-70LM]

## ispLSI3320-70LM
designator U?
In-System Programmable High-Density PLD
footprint MQFP208_N (Shrink QFP, 208-Leads, Body 27.7x27.7mm, Pitch 0.5mm, IPC Medium Density)
footprint MQFP208_L (Shrink QFP, 208-Leads, Body 27.7x27.7mm, Pitch 0.5mm, IPC High Density)
footprint MQFP208_M (Shrink QFP, 208-Leads, Body 27.7x27.7mm, Pitch 0.5mm, IPC Low Density)
3D model 3320-MQFP208 (208-Pin Shrink Quad Flat Pack 0.5 mm Pitch)
part A pins: 1 I/O140 (io), 2 I/O141 (io), 3 I/O142 (io), 4 I/O143 (io), 5 I/O144 (io), 6 I/O145 (io), 7 I/O146 (io), 8 I/O147 (io), 9 I/O148 (io), 10 I/O149 (io), 12 I/O150 (io), 13 I/O151 (io), 15 I/O152 (io), 16 I/O153 (io), 17 I/O154 (io), 18 I/O155 (io), 19 I/O156 (io), 20 I/O157 (io), 21 I/O158 (io), 22 I/O159 (io), 23 MODE/TMS (in), 24 SCLK/TCK (in), 25 SDI/TDI (in), 27 ~{ispEN}/BSCAN (in), 28 ~{RESET} (in), 29 ~{TRST}/NC (in), 30 TOE (in), 31 I/O0 (io), 32 I/O1 (io), 33 I/O2 (io), 34 I/O3 (io), 35 I/O4 (io), 36 I/O5 (io), 37 I/O6 (io), 38 I/O7 (io), 40 I/O8 (io), 41 I/O9 (io), 43 I/O10 (io), 44 I/O11 (io), 45 I/O12 (io), 46 I/O13 (io), 47 I/O14 (io), 48 I/O15 (io), 49 I/O16 (io), 50 I/O17 (io), 51 I/O18 (io), 52 I/O19 (io), 54 I/O20 (io), 55 I/O21 (io), 56 I/O22 (io), 57 I/O23 (io), 59 I/O24 (io), 60 I/O25 (io), 61 I/O26 (io), 62 I/O27 (io), 63 I/O28 (io), 64 I/O29 (io), 66 I/O30 (io), 67 I/O31 (io), 68 I/O32 (io), 69 I/O33 (io), 70 I/O34 (io), 71 I/O35 (io), 72 I/O36 (io), 73 I/O37 (io), 74 I/O38 (io), 75 I/O39 (io), 82 I/O40 (io), 83 I/O41 (io), 84 I/O42 (io), 85 I/O43 (io), 86 I/O44 (io), 87 I/O45 (io), 88 I/O46 (io), 89 I/O47 (io), 90 I/O48 (io), 91 I/O49 (io), 93 I/O50 (io), 94 I/O51 (io), 95 I/O52 (io), 96 I/O53 (io), 97 I/O54 (io), 98 I/O55 (io), 100 I/O56 (io), 101 I/O57 (io), 102 I/O58 (io), 103 I/O59 (io), 105 I/O60 (io), 106 I/O61 (io), 107 I/O62 (io), 108 I/O63 (io), 109 I/O64 (io), 110 I/O65 (io), 111 I/O66 (io), 112 I/O67 (io), 113 I/O68 (io), 114 I/O69 (io), 116 I/O70 (io), 117 I/O71 (io), 119 I/O72 (io), 120 I/O73 (io), 121 I/O74 (io), 122 I/O75 (io), 123 I/O76 (io), 124 I/O77 (io), 125 I/O78 (io), 126 I/O79 (io), 127 Y4 (in), 128 Y3 (in), 129 Y2 (in), 130 Y1 (in), 132 Y0 (in), 133 GOE0 (in), 134 GOE1 (in), 135 I/O80 (io), 136 I/O81 (io), 137 I/O82 (io), 138 I/O83 (io), 139 I/O84 (io), 140 I/O85 (io), 141 I/O86 (io), 142 I/O87 (io), 144 I/O88 (io), 145 I/O89 (io), 147 I/O90 (io), 148 I/O91 (io), 149 I/O92 (io), 150 I/O93 (io), 151 I/O94 (io), 152 I/O95 (io), 153 I/O96 (io), 154 I/O97 (io), 155 I/O98 (io), 156 I/O99 (io), 158 I/O100 (io), 159 I/O101 (io), 160 I/O102 (io), 161 I/O103 (io), 163 I/O104 (io), 164 I/O105 (io), 165 I/O106 (io), 166 I/O107 (io), 167 I/O108 (io), 168 I/O109 (io), 170 I/O110 (io), 171 I/O111 (io), 172 I/O112 (io), 173 I/O113 (io), 174 I/O114 (io), 175 I/O115 (io), 176 I/O116 (io), 177 I/O117 (io), 178 I/O118 (io), 179 I/O119 (io), 185 SDO/TDO (out), 186 I/O120 (io), 187 I/O121 (io), 188 I/O122 (io), 189 I/O123 (io), 190 I/O124 (io), 191 I/O125 (io), 192 I/O126 (io), 193 I/O127 (io), 194 I/O128 (io), 195 I/O129 (io), 197 I/O130 (io), 198 I/O131 (io), 199 I/O132 (io), 200 I/O133 (io), 201 I/O134 (io), 202 I/O135 (io), 204 I/O136 (io), 205 I/O137 (io), 206 I/O138 (io), 207 I/O139 (io)
part B pins: 11 GND (power), 14 VCC (power), 26 GND (power), 39 VCC (power), 42 GND (power), 53 GND (power), 58 VCC (power), 65 GND (power), 76 NC, 77 NC, 78 GND (power), 79 NC, 80 VCC (power), 81 NC, 92 GND (power), 99 VCC (power), 104 GND (power), 115 GND (power), 118 VCC (power), 131 GND (power), 143 VCC (power), 146 GND (power), 157 GND (power), 162 VCC (power), 169 GND (power), 180 NC, 181 VCC (power), 182 NC, 183 GND (power), 184 NC, 196 GND (power), 203 VCC (power), 208 GND (power)

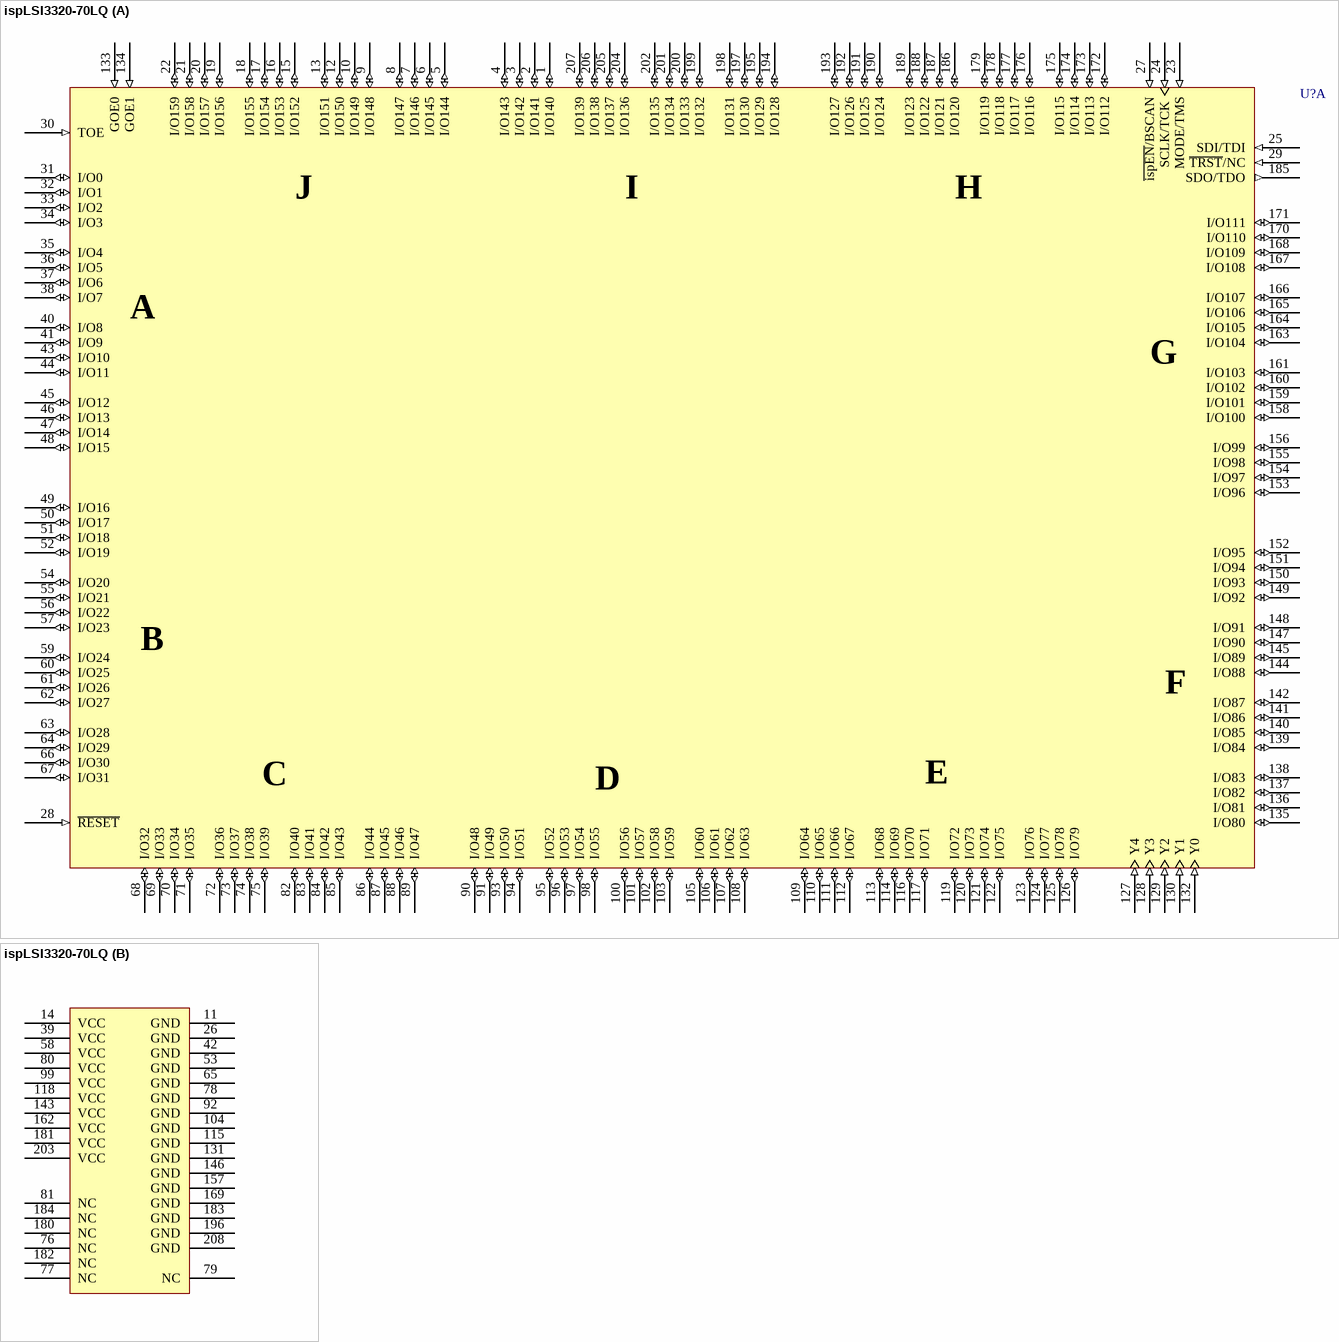
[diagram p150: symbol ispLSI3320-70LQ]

## ispLSI3320-70LQ
designator U?
In-System Programmable High-Density PLD
footprint PQFP208_N (Shrink QFP, 208-Leads, Body 28x28mm, Pitch 0.5mm, IPC Medium Density)
footprint PQFP208_L (Shrink QFP, 208-Leads, Body 28x28mm, Pitch 0.5mm, IPC High Density)
footprint PQFP208_M (Shrink QFP, 208-Leads, Body 28x28mm, Pitch 0.5mm, IPC Low Density)
3D model 3320-PQFP208 (208-Pin Plastic Quad Flat Pack (PQFP208))
part A pins: 1 I/O140 (io), 2 I/O141 (io), 3 I/O142 (io), 4 I/O143 (io), 5 I/O144 (io), 6 I/O145 (io), 7 I/O146 (io), 8 I/O147 (io), 9 I/O148 (io), 10 I/O149 (io), 12 I/O150 (io), 13 I/O151 (io), 15 I/O152 (io), 16 I/O153 (io), 17 I/O154 (io), 18 I/O155 (io), 19 I/O156 (io), 20 I/O157 (io), 21 I/O158 (io), 22 I/O159 (io), 23 MODE/TMS (in), 24 SCLK/TCK (in), 25 SDI/TDI (in), 27 ~{ispEN}/BSCAN (in), 28 ~{RESET} (in), 29 ~{TRST}/NC (in), 30 TOE (in), 31 I/O0 (io), 32 I/O1 (io), 33 I/O2 (io), 34 I/O3 (io), 35 I/O4 (io), 36 I/O5 (io), 37 I/O6 (io), 38 I/O7 (io), 40 I/O8 (io), 41 I/O9 (io), 43 I/O10 (io), 44 I/O11 (io), 45 I/O12 (io), 46 I/O13 (io), 47 I/O14 (io), 48 I/O15 (io), 49 I/O16 (io), 50 I/O17 (io), 51 I/O18 (io), 52 I/O19 (io), 54 I/O20 (io), 55 I/O21 (io), 56 I/O22 (io), 57 I/O23 (io), 59 I/O24 (io), 60 I/O25 (io), 61 I/O26 (io), 62 I/O27 (io), 63 I/O28 (io), 64 I/O29 (io), 66 I/O30 (io), 67 I/O31 (io), 68 I/O32 (io), 69 I/O33 (io), 70 I/O34 (io), 71 I/O35 (io), 72 I/O36 (io), 73 I/O37 (io), 74 I/O38 (io), 75 I/O39 (io), 82 I/O40 (io), 83 I/O41 (io), 84 I/O42 (io), 85 I/O43 (io), 86 I/O44 (io), 87 I/O45 (io), 88 I/O46 (io), 89 I/O47 (io), 90 I/O48 (io), 91 I/O49 (io), 93 I/O50 (io), 94 I/O51 (io), 95 I/O52 (io), 96 I/O53 (io), 97 I/O54 (io), 98 I/O55 (io), 100 I/O56 (io), 101 I/O57 (io), 102 I/O58 (io), 103 I/O59 (io), 105 I/O60 (io), 106 I/O61 (io), 107 I/O62 (io), 108 I/O63 (io), 109 I/O64 (io), 110 I/O65 (io), 111 I/O66 (io), 112 I/O67 (io), 113 I/O68 (io), 114 I/O69 (io), 116 I/O70 (io), 117 I/O71 (io), 119 I/O72 (io), 120 I/O73 (io), 121 I/O74 (io), 122 I/O75 (io), 123 I/O76 (io), 124 I/O77 (io), 125 I/O78 (io), 126 I/O79 (io), 127 Y4 (in), 128 Y3 (in), 129 Y2 (in), 130 Y1 (in), 132 Y0 (in), 133 GOE0 (in), 134 GOE1 (in), 135 I/O80 (io), 136 I/O81 (io), 137 I/O82 (io), 138 I/O83 (io), 139 I/O84 (io), 140 I/O85 (io), 141 I/O86 (io), 142 I/O87 (io), 144 I/O88 (io), 145 I/O89 (io), 147 I/O90 (io), 148 I/O91 (io), 149 I/O92 (io), 150 I/O93 (io), 151 I/O94 (io), 152 I/O95 (io), 153 I/O96 (io), 154 I/O97 (io), 155 I/O98 (io), 156 I/O99 (io), 158 I/O100 (io), 159 I/O101 (io), 160 I/O102 (io), 161 I/O103 (io), 163 I/O104 (io), 164 I/O105 (io), 165 I/O106 (io), 166 I/O107 (io), 167 I/O108 (io), 168 I/O109 (io), 170 I/O110 (io), 171 I/O111 (io), 172 I/O112 (io), 173 I/O113 (io), 174 I/O114 (io), 175 I/O115 (io), 176 I/O116 (io), 177 I/O117 (io), 178 I/O118 (io), 179 I/O119 (io), 185 SDO/TDO (out), 186 I/O120 (io), 187 I/O121 (io), 188 I/O122 (io), 189 I/O123 (io), 190 I/O124 (io), 191 I/O125 (io), 192 I/O126 (io), 193 I/O127 (io), 194 I/O128 (io), 195 I/O129 (io), 197 I/O130 (io), 198 I/O131 (io), 199 I/O132 (io), 200 I/O133 (io), 201 I/O134 (io), 202 I/O135 (io), 204 I/O136 (io), 205 I/O137 (io), 206 I/O138 (io), 207 I/O139 (io)
part B pins: 11 GND (power), 14 VCC (power), 26 GND (power), 39 VCC (power), 42 GND (power), 53 GND (power), 58 VCC (power), 65 GND (power), 76 NC, 77 NC, 78 GND (power), 79 NC, 80 VCC (power), 81 NC, 92 GND (power), 99 VCC (power), 104 GND (power), 115 GND (power), 118 VCC (power), 131 GND (power), 143 VCC (power), 146 GND (power), 157 GND (power), 162 VCC (power), 169 GND (power), 180 NC, 181 VCC (power), 182 NC, 183 GND (power), 184 NC, 196 GND (power), 203 VCC (power), 208 GND (power)

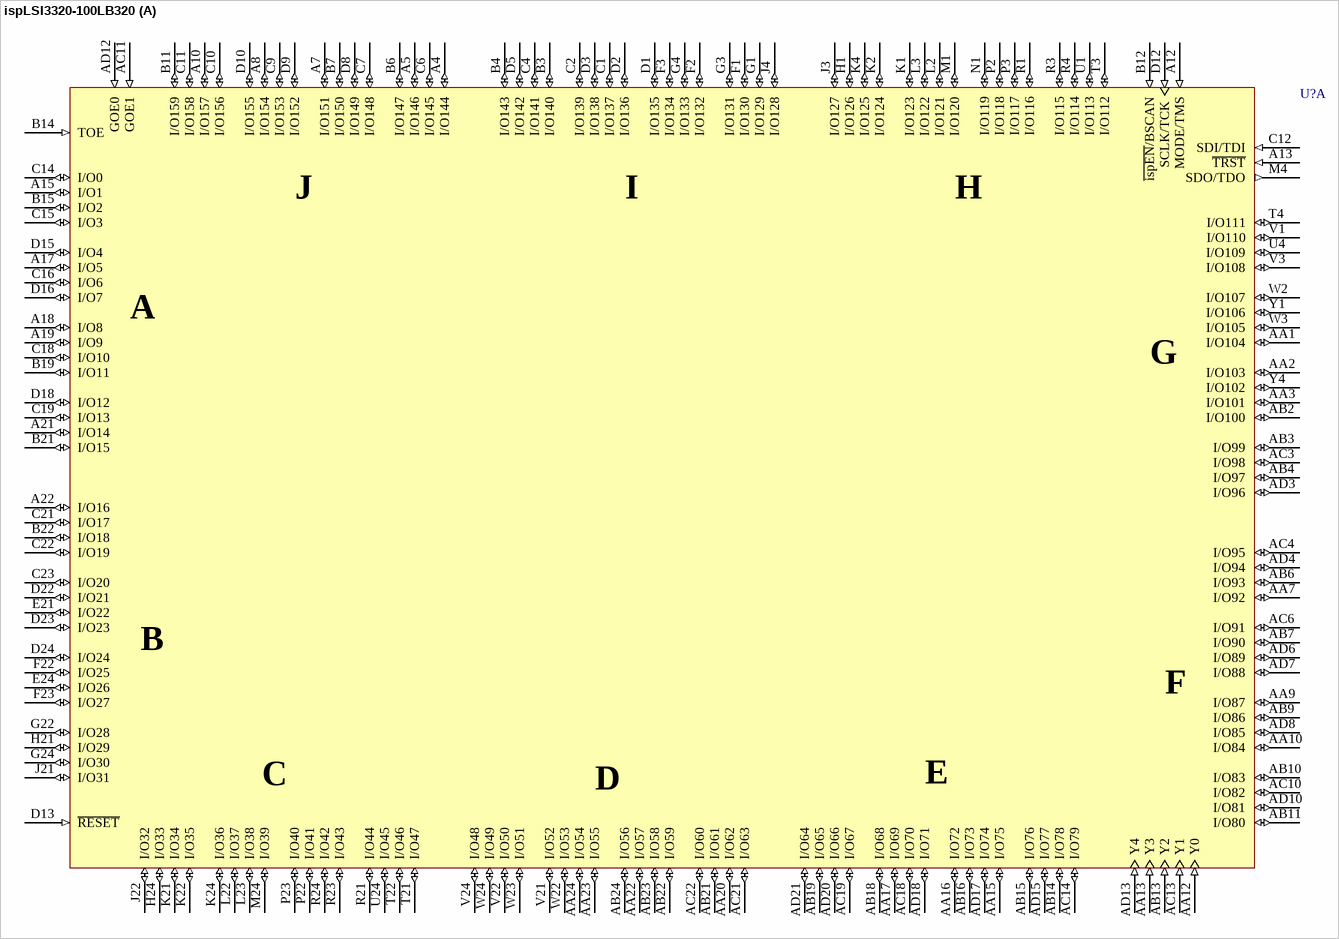
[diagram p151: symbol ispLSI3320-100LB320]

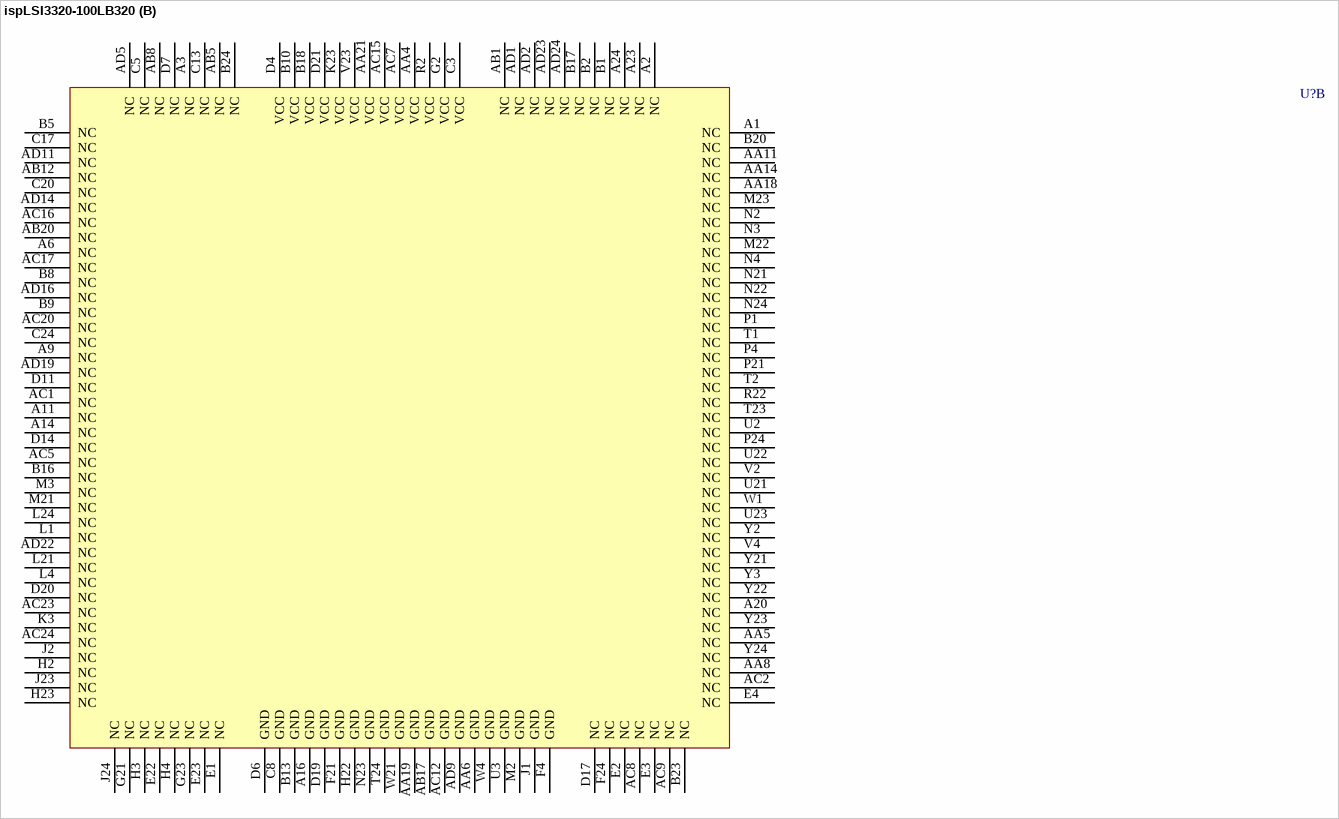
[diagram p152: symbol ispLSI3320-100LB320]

## ispLSI3320-100LB320
designator U?
In-System Programmable High-Density PLD
footprint SBGA320 (BGA, 320-Leads, Body 31x31mm, Pitch 1.27mm)
3D model 3320-SBGA320 (320-Ball Super Ball Grid Array (SBGA320))
part A pins: A4 I/O144 (io), A5 I/O146 (io), A7 I/O151 (io), A8 I/O154 (io), A10 I/O157 (io), A12 MODE/TMS (in), A13 ~{TRST} (in), A15 I/O1 (io), A17 I/O5 (io), A18 I/O8 (io), A19 I/O9 (io), A21 I/O14 (io), A22 I/O16 (io), AA1 I/O104 (io), AA2 I/O103 (io), AA3 I/O101 (io), AA7 I/O92 (io), AA9 I/O87 (io), AA10 I/O84 (io), AA12 Y0 (in), AA13 Y3 (in), AA15 I/O75 (io), AA16 I/O72 (io), AA17 I/O69 (io), AA20 I/O62 (io), AA22 I/O57 (io), AA23 I/O55 (io), AA24 I/O54 (io), AB2 I/O100 (io), AB3 I/O99 (io), AB4 I/O97 (io), AB6 I/O93 (io), AB7 I/O90 (io), AB9 I/O86 (io), AB10 I/O83 (io), AB11 I/O80 (io), AB13 Y2 (in), AB14 I/O78 (io), AB15 I/O76 (io), AB16 I/O73 (io), AB18 I/O68 (io), AB19 I/O65 (io), AB21 I/O61 (io), AB22 I/O59 (io), AB23 I/O58 (io), AB24 I/O56 (io), AC3 I/O98 (io), AC4 I/O95 (io), AC6 I/O91 (io), AC10 I/O82 (io), AC11 GOE1 (in), AC13 Y1 (in), AC14 I/O79 (io), AC18 I/O70 (io), AC19 I/O67 (io), AC21 I/O63 (io), AC22 I/O60 (io), AD3 I/O96 (io), AD4 I/O94 (io), AD6 I/O89 (io), AD7 I/O88 (io), AD8 I/O85 (io), AD10 I/O81 (io), AD12 GOE0 (in), AD13 Y4 (in), AD15 I/O77 (io), AD17 I/O74 (io), AD18 I/O71 (io), AD20 I/O66 (io), AD21 I/O64 (io), B3 I/O140 (io), B4 I/O143 (io), B6 I/O147 (io), B7 I/O150 (io), B11 I/O159 (io), B12 ~{ispEN}/BSCAN (in), B14 TOE (in), B15 I/O2 (io), B19 I/O11 (io), B21 I/O15 (io), B22 I/O18 (io), C1 I/O137 (io), C2 I/O139 (io), C4 I/O141 (io), C6 I/O145 (io), C7 I/O148 (io), C9 I/O153 (io), C10 I/O156 (io), C11 I/O158 (io), C12 SDI/TDI (in), C14 I/O0 (io), C15 I/O3 (io), C16 I/O6 (io), C18 I/O10 (io), C19 I/O13 (io), C21 I/O17 (io), C22 I/O19 (io), C23 I/O20 (io), D1 I/O135 (io), D2 I/O136 (io), D3 I/O138 (io), D5 I/O142 (io), D8 I/O149 (io), D9 I/O152 (io), D10 I/O155 (io), D12 SCLK/TCK (in), D13 ~{RESET} (in), D15 I/O4 (io), D16 I/O7 (io), D18 I/O12 (io), D22 I/O21 (io), D23 I/O23 (io), D24 I/O24 (io), E21 I/O22 (io), E24 I/O26 (io), F1 I/O130 (io), F2 I/O132 (io), F3 I/O134 (io), F22 I/O25 (io), F23 I/O27 (io), G1 I/O129 (io), G3 I/O131 (io), G4 I/O133 (io), G22 I/O28 (io), G24 I/O30 (io), H1 I/O126 (io), H21 I/O29 (io), H24 I/O33 (io), J3 I/O127 (io), J4 I/O128 (io), J21 I/O31 (io), J22 I/O32 (io), K1 I/O123 (io), K2 I/O124 (io), K4 I/O125 (io), K21 I/O34 (io), K22 I/O35 (io), K24 I/O36 (io), L2 I/O121 (io), L3 I/O122 (io), L22 I/O37 (io), L23 I/O38 (io), M1 I/O120 (io), M4 SDO/TDO (out), M24 I/O39 (io), N1 I/O119 (io), P2 I/O118 (io), P3 I/O117 (io), P22 I/O41 (io), P23 I/O40 (io), R1 I/O116 (io), R3 I/O115 (io), R4 I/O114 (io), R21 I/O44 (io), R23 I/O43 (io), R24 I/O42 (io), T3 I/O112 (io), T4 I/O111 (io), T21 I/O47 (io), T22 I/O46 (io), U1 I/O113 (io), U4 I/O109 (io), U24 I/O45 (io), V1 I/O110 (io), V3 I/O108 (io), V21 I/O52 (io), V22 I/O50 (io), V24 I/O48 (io), W2 I/O107 (io), W3 I/O105 (io), W22 I/O53 (io), W23 I/O51 (io), W24 I/O49 (io), Y1 I/O106 (io), Y4 I/O102 (io)
part B pins: A1 NC, A2 NC, A3 NC, A6 NC, A9 NC, A11 NC, A14 NC, A16 GND (power), A20 NC, A23 NC, A24 NC, AA4 VCC (power), AA5 NC, AA6 GND (power), AA8 NC, AA11 NC, AA14 NC, AA18 NC, AA19 GND (power), AA21 VCC (power), AB1 NC, AB5 NC, AB8 NC, AB12 NC, AB17 GND (power), AB20 NC, AC1 NC, AC2 NC, AC5 NC, AC7 VCC (power), AC8 NC, AC9 NC, AC12 GND (power), AC15 VCC (power), AC16 NC, AC17 NC, AC20 NC, AC23 NC, AC24 NC, AD1 NC, AD2 NC, AD5 NC, AD9 GND (power), AD11 NC, AD14 NC, AD16 NC, AD19 NC, AD22 NC, AD23 NC, AD24 NC, B1 NC, B2 NC, B5 NC, B8 NC, B9 NC, B10 VCC (power), B13 GND (power), B16 NC, B17 NC, B18 VCC (power), B20 NC, B23 NC, B24 NC, C3 VCC (power), C5 NC, C8 GND (power), C13 NC, C17 NC, C20 NC, C24 NC, D4 VCC (power), D6 GND (power), D7 NC, D11 NC, D14 NC, D17 NC, D19 GND (power), D20 NC, D21 VCC (power), E1 NC, E2 NC, E3 NC, E4 NC, E22 NC, E23 NC, F4 GND (power), F21 GND (power), F24 NC, G2 VCC (power), G21 NC, G23 NC, H2 NC, H3 NC, H4 NC, H22 GND (power), H23 NC, J1 GND (power), J2 NC, J23 NC, J24 NC, K3 NC, K23 VCC (power), L1 NC, L4 NC, L21 NC, L24 NC, M2 GND (power), M3 NC, M21 NC, M22 NC, M23 NC, N2 NC, N3 NC, N4 NC, N21 NC, N22 NC, N23 GND (power), N24 NC, P1 NC, P4 NC, P21 NC, P24 NC, R2 VCC (power), R22 NC, T1 NC, T2 NC, T23 NC, T24 GND (power), U2 NC, U3 GND (power), U21 NC, U22 NC, U23 NC, V2 NC, V4 NC, V23 VCC (power), W1 NC, W4 GND (power), W21 GND (power), Y2 NC, Y3 NC, Y21 NC, Y22 NC, Y23 NC, Y24 NC

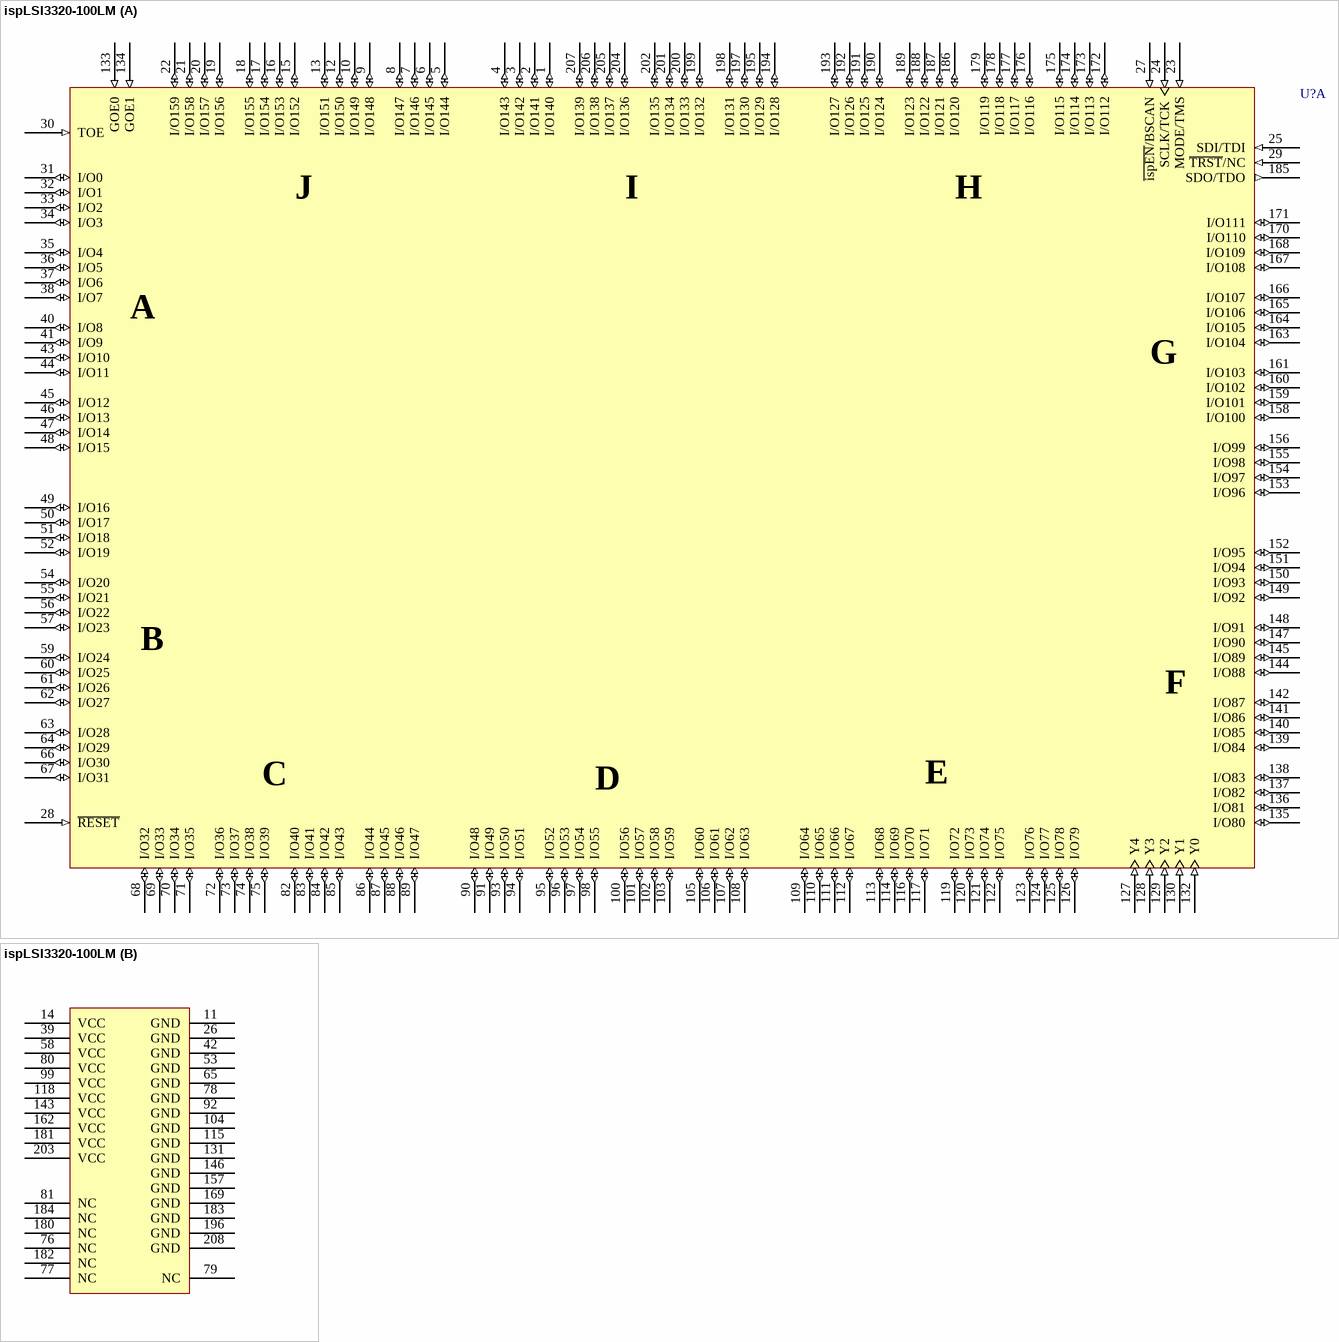
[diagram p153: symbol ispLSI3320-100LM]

## ispLSI3320-100LM
designator U?
In-System Programmable High-Density PLD
footprint MQFP208_N (Shrink QFP, 208-Leads, Body 27.7x27.7mm, Pitch 0.5mm, IPC Medium Density)
footprint MQFP208_L (Shrink QFP, 208-Leads, Body 27.7x27.7mm, Pitch 0.5mm, IPC High Density)
footprint MQFP208_M (Shrink QFP, 208-Leads, Body 27.7x27.7mm, Pitch 0.5mm, IPC Low Density)
3D model 3320-MQFP208 (208-Pin Shrink Quad Flat Pack 0.5 mm Pitch)
part A pins: 1 I/O140 (io), 2 I/O141 (io), 3 I/O142 (io), 4 I/O143 (io), 5 I/O144 (io), 6 I/O145 (io), 7 I/O146 (io), 8 I/O147 (io), 9 I/O148 (io), 10 I/O149 (io), 12 I/O150 (io), 13 I/O151 (io), 15 I/O152 (io), 16 I/O153 (io), 17 I/O154 (io), 18 I/O155 (io), 19 I/O156 (io), 20 I/O157 (io), 21 I/O158 (io), 22 I/O159 (io), 23 MODE/TMS (in), 24 SCLK/TCK (in), 25 SDI/TDI (in), 27 ~{ispEN}/BSCAN (in), 28 ~{RESET} (in), 29 ~{TRST}/NC (in), 30 TOE (in), 31 I/O0 (io), 32 I/O1 (io), 33 I/O2 (io), 34 I/O3 (io), 35 I/O4 (io), 36 I/O5 (io), 37 I/O6 (io), 38 I/O7 (io), 40 I/O8 (io), 41 I/O9 (io), 43 I/O10 (io), 44 I/O11 (io), 45 I/O12 (io), 46 I/O13 (io), 47 I/O14 (io), 48 I/O15 (io), 49 I/O16 (io), 50 I/O17 (io), 51 I/O18 (io), 52 I/O19 (io), 54 I/O20 (io), 55 I/O21 (io), 56 I/O22 (io), 57 I/O23 (io), 59 I/O24 (io), 60 I/O25 (io), 61 I/O26 (io), 62 I/O27 (io), 63 I/O28 (io), 64 I/O29 (io), 66 I/O30 (io), 67 I/O31 (io), 68 I/O32 (io), 69 I/O33 (io), 70 I/O34 (io), 71 I/O35 (io), 72 I/O36 (io), 73 I/O37 (io), 74 I/O38 (io), 75 I/O39 (io), 82 I/O40 (io), 83 I/O41 (io), 84 I/O42 (io), 85 I/O43 (io), 86 I/O44 (io), 87 I/O45 (io), 88 I/O46 (io), 89 I/O47 (io), 90 I/O48 (io), 91 I/O49 (io), 93 I/O50 (io), 94 I/O51 (io), 95 I/O52 (io), 96 I/O53 (io), 97 I/O54 (io), 98 I/O55 (io), 100 I/O56 (io), 101 I/O57 (io), 102 I/O58 (io), 103 I/O59 (io), 105 I/O60 (io), 106 I/O61 (io), 107 I/O62 (io), 108 I/O63 (io), 109 I/O64 (io), 110 I/O65 (io), 111 I/O66 (io), 112 I/O67 (io), 113 I/O68 (io), 114 I/O69 (io), 116 I/O70 (io), 117 I/O71 (io), 119 I/O72 (io), 120 I/O73 (io), 121 I/O74 (io), 122 I/O75 (io), 123 I/O76 (io), 124 I/O77 (io), 125 I/O78 (io), 126 I/O79 (io), 127 Y4 (in), 128 Y3 (in), 129 Y2 (in), 130 Y1 (in), 132 Y0 (in), 133 GOE0 (in), 134 GOE1 (in), 135 I/O80 (io), 136 I/O81 (io), 137 I/O82 (io), 138 I/O83 (io), 139 I/O84 (io), 140 I/O85 (io), 141 I/O86 (io), 142 I/O87 (io), 144 I/O88 (io), 145 I/O89 (io), 147 I/O90 (io), 148 I/O91 (io), 149 I/O92 (io), 150 I/O93 (io), 151 I/O94 (io), 152 I/O95 (io), 153 I/O96 (io), 154 I/O97 (io), 155 I/O98 (io), 156 I/O99 (io), 158 I/O100 (io), 159 I/O101 (io), 160 I/O102 (io), 161 I/O103 (io), 163 I/O104 (io), 164 I/O105 (io), 165 I/O106 (io), 166 I/O107 (io), 167 I/O108 (io), 168 I/O109 (io), 170 I/O110 (io), 171 I/O111 (io), 172 I/O112 (io), 173 I/O113 (io), 174 I/O114 (io), 175 I/O115 (io), 176 I/O116 (io), 177 I/O117 (io), 178 I/O118 (io), 179 I/O119 (io), 185 SDO/TDO (out), 186 I/O120 (io), 187 I/O121 (io), 188 I/O122 (io), 189 I/O123 (io), 190 I/O124 (io), 191 I/O125 (io), 192 I/O126 (io), 193 I/O127 (io), 194 I/O128 (io), 195 I/O129 (io), 197 I/O130 (io), 198 I/O131 (io), 199 I/O132 (io), 200 I/O133 (io), 201 I/O134 (io), 202 I/O135 (io), 204 I/O136 (io), 205 I/O137 (io), 206 I/O138 (io), 207 I/O139 (io)
part B pins: 11 GND (power), 14 VCC (power), 26 GND (power), 39 VCC (power), 42 GND (power), 53 GND (power), 58 VCC (power), 65 GND (power), 76 NC, 77 NC, 78 GND (power), 79 NC, 80 VCC (power), 81 NC, 92 GND (power), 99 VCC (power), 104 GND (power), 115 GND (power), 118 VCC (power), 131 GND (power), 143 VCC (power), 146 GND (power), 157 GND (power), 162 VCC (power), 169 GND (power), 180 NC, 181 VCC (power), 182 NC, 183 GND (power), 184 NC, 196 GND (power), 203 VCC (power), 208 GND (power)

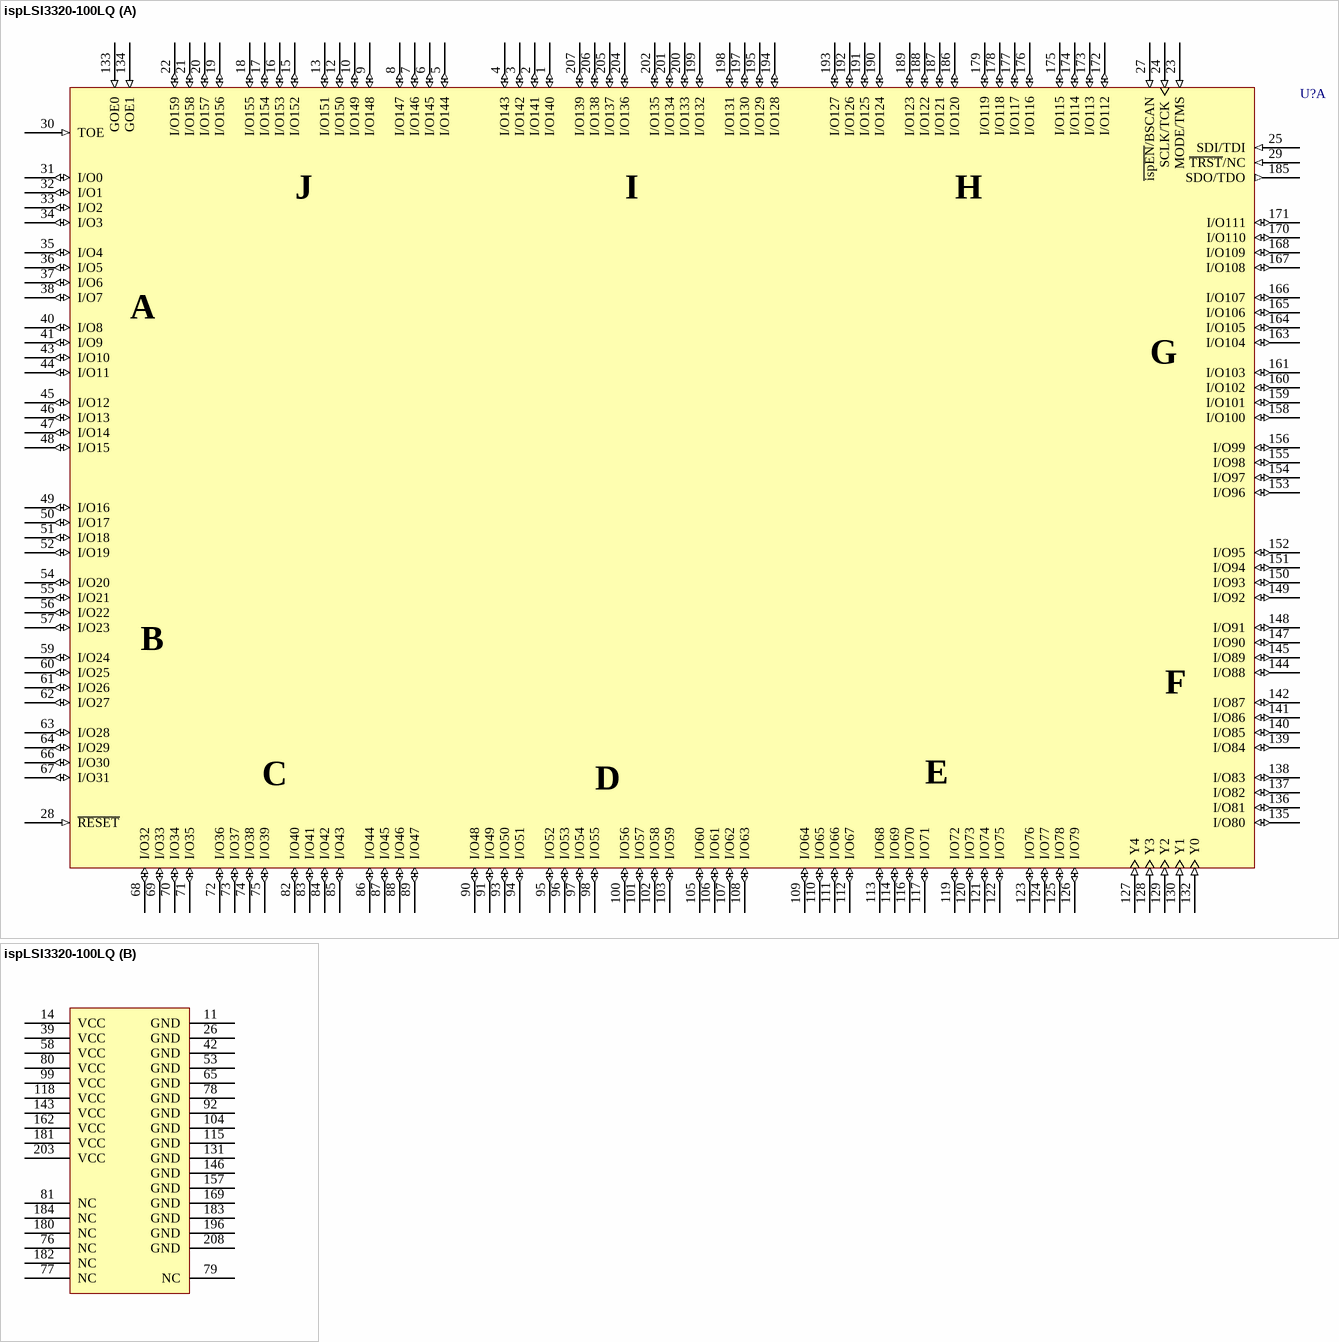
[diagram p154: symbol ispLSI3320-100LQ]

## ispLSI3320-100LQ
designator U?
In-System Programmable High-Density PLD
footprint PQFP208_N (Shrink QFP, 208-Leads, Body 28x28mm, Pitch 0.5mm, IPC Medium Density)
footprint PQFP208_L (Shrink QFP, 208-Leads, Body 28x28mm, Pitch 0.5mm, IPC High Density)
footprint PQFP208_M (Shrink QFP, 208-Leads, Body 28x28mm, Pitch 0.5mm, IPC Low Density)
3D model 3320-PQFP208 (208-Pin Plastic Quad Flat Pack (PQFP208))
part A pins: 1 I/O140 (io), 2 I/O141 (io), 3 I/O142 (io), 4 I/O143 (io), 5 I/O144 (io), 6 I/O145 (io), 7 I/O146 (io), 8 I/O147 (io), 9 I/O148 (io), 10 I/O149 (io), 12 I/O150 (io), 13 I/O151 (io), 15 I/O152 (io), 16 I/O153 (io), 17 I/O154 (io), 18 I/O155 (io), 19 I/O156 (io), 20 I/O157 (io), 21 I/O158 (io), 22 I/O159 (io), 23 MODE/TMS (in), 24 SCLK/TCK (in), 25 SDI/TDI (in), 27 ~{ispEN}/BSCAN (in), 28 ~{RESET} (in), 29 ~{TRST}/NC (in), 30 TOE (in), 31 I/O0 (io), 32 I/O1 (io), 33 I/O2 (io), 34 I/O3 (io), 35 I/O4 (io), 36 I/O5 (io), 37 I/O6 (io), 38 I/O7 (io), 40 I/O8 (io), 41 I/O9 (io), 43 I/O10 (io), 44 I/O11 (io), 45 I/O12 (io), 46 I/O13 (io), 47 I/O14 (io), 48 I/O15 (io), 49 I/O16 (io), 50 I/O17 (io), 51 I/O18 (io), 52 I/O19 (io), 54 I/O20 (io), 55 I/O21 (io), 56 I/O22 (io), 57 I/O23 (io), 59 I/O24 (io), 60 I/O25 (io), 61 I/O26 (io), 62 I/O27 (io), 63 I/O28 (io), 64 I/O29 (io), 66 I/O30 (io), 67 I/O31 (io), 68 I/O32 (io), 69 I/O33 (io), 70 I/O34 (io), 71 I/O35 (io), 72 I/O36 (io), 73 I/O37 (io), 74 I/O38 (io), 75 I/O39 (io), 82 I/O40 (io), 83 I/O41 (io), 84 I/O42 (io), 85 I/O43 (io), 86 I/O44 (io), 87 I/O45 (io), 88 I/O46 (io), 89 I/O47 (io), 90 I/O48 (io), 91 I/O49 (io), 93 I/O50 (io), 94 I/O51 (io), 95 I/O52 (io), 96 I/O53 (io), 97 I/O54 (io), 98 I/O55 (io), 100 I/O56 (io), 101 I/O57 (io), 102 I/O58 (io), 103 I/O59 (io), 105 I/O60 (io), 106 I/O61 (io), 107 I/O62 (io), 108 I/O63 (io), 109 I/O64 (io), 110 I/O65 (io), 111 I/O66 (io), 112 I/O67 (io), 113 I/O68 (io), 114 I/O69 (io), 116 I/O70 (io), 117 I/O71 (io), 119 I/O72 (io), 120 I/O73 (io), 121 I/O74 (io), 122 I/O75 (io), 123 I/O76 (io), 124 I/O77 (io), 125 I/O78 (io), 126 I/O79 (io), 127 Y4 (in), 128 Y3 (in), 129 Y2 (in), 130 Y1 (in), 132 Y0 (in), 133 GOE0 (in), 134 GOE1 (in), 135 I/O80 (io), 136 I/O81 (io), 137 I/O82 (io), 138 I/O83 (io), 139 I/O84 (io), 140 I/O85 (io), 141 I/O86 (io), 142 I/O87 (io), 144 I/O88 (io), 145 I/O89 (io), 147 I/O90 (io), 148 I/O91 (io), 149 I/O92 (io), 150 I/O93 (io), 151 I/O94 (io), 152 I/O95 (io), 153 I/O96 (io), 154 I/O97 (io), 155 I/O98 (io), 156 I/O99 (io), 158 I/O100 (io), 159 I/O101 (io), 160 I/O102 (io), 161 I/O103 (io), 163 I/O104 (io), 164 I/O105 (io), 165 I/O106 (io), 166 I/O107 (io), 167 I/O108 (io), 168 I/O109 (io), 170 I/O110 (io), 171 I/O111 (io), 172 I/O112 (io), 173 I/O113 (io), 174 I/O114 (io), 175 I/O115 (io), 176 I/O116 (io), 177 I/O117 (io), 178 I/O118 (io), 179 I/O119 (io), 185 SDO/TDO (out), 186 I/O120 (io), 187 I/O121 (io), 188 I/O122 (io), 189 I/O123 (io), 190 I/O124 (io), 191 I/O125 (io), 192 I/O126 (io), 193 I/O127 (io), 194 I/O128 (io), 195 I/O129 (io), 197 I/O130 (io), 198 I/O131 (io), 199 I/O132 (io), 200 I/O133 (io), 201 I/O134 (io), 202 I/O135 (io), 204 I/O136 (io), 205 I/O137 (io), 206 I/O138 (io), 207 I/O139 (io)
part B pins: 11 GND (power), 14 VCC (power), 26 GND (power), 39 VCC (power), 42 GND (power), 53 GND (power), 58 VCC (power), 65 GND (power), 76 NC, 77 NC, 78 GND (power), 79 NC, 80 VCC (power), 81 NC, 92 GND (power), 99 VCC (power), 104 GND (power), 115 GND (power), 118 VCC (power), 131 GND (power), 143 VCC (power), 146 GND (power), 157 GND (power), 162 VCC (power), 169 GND (power), 180 NC, 181 VCC (power), 182 NC, 183 GND (power), 184 NC, 196 GND (power), 203 VCC (power), 208 GND (power)

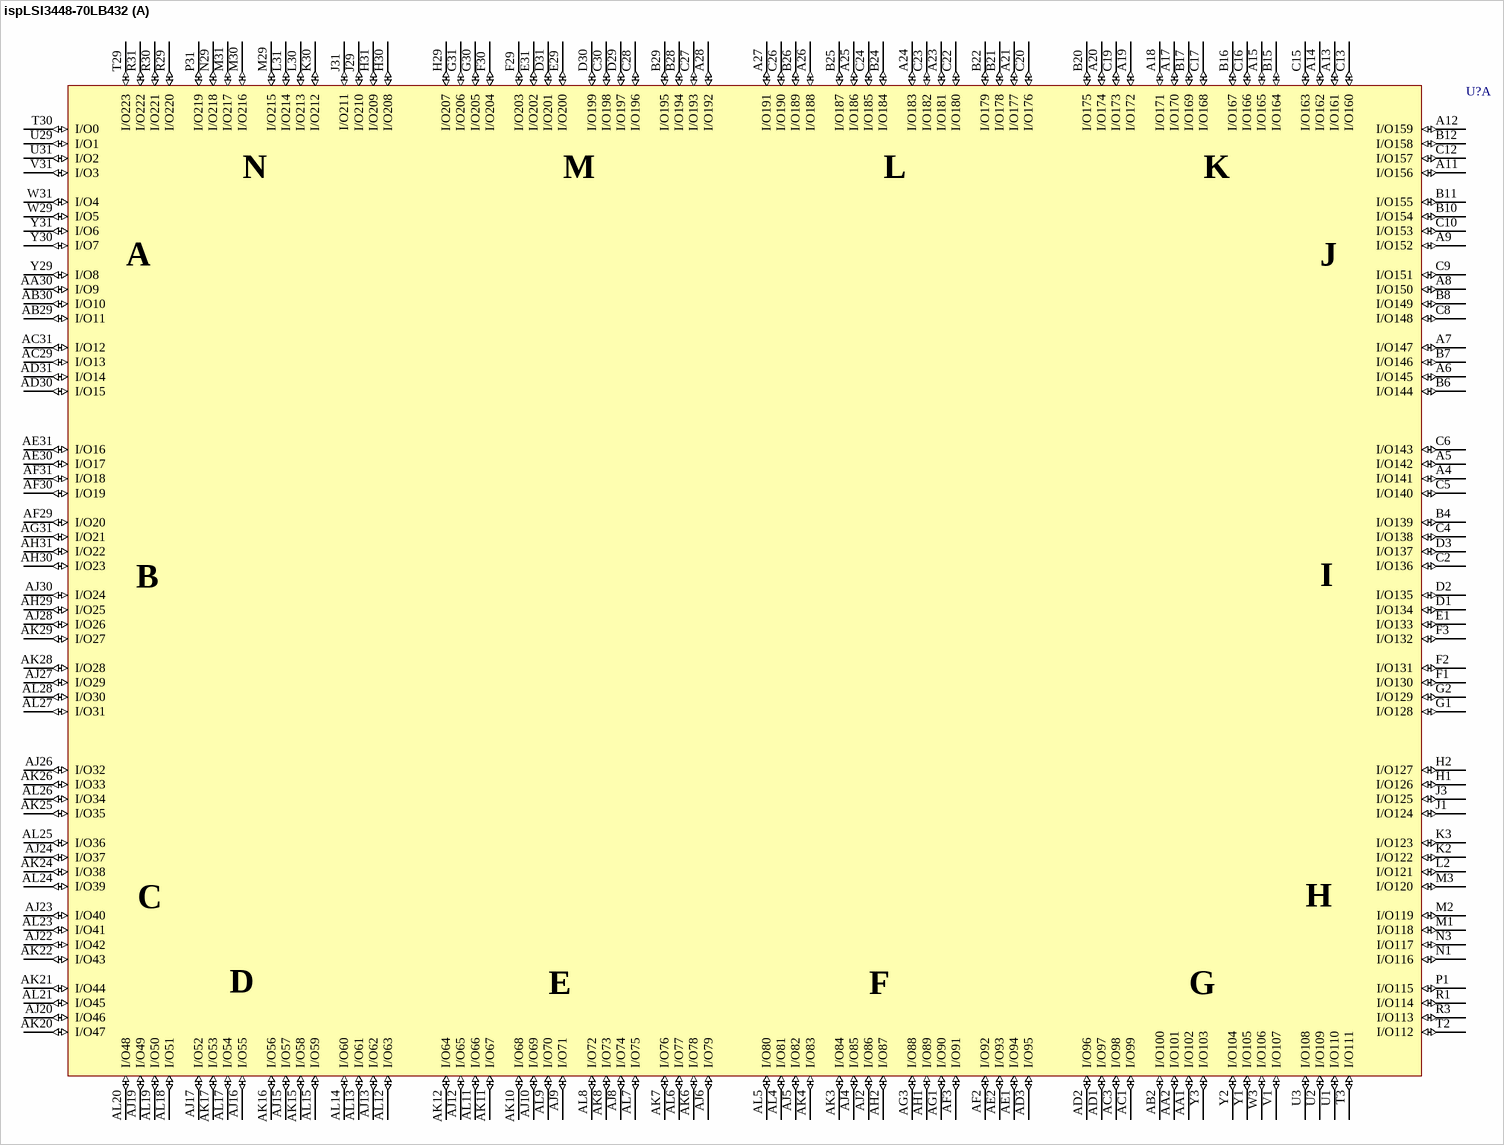
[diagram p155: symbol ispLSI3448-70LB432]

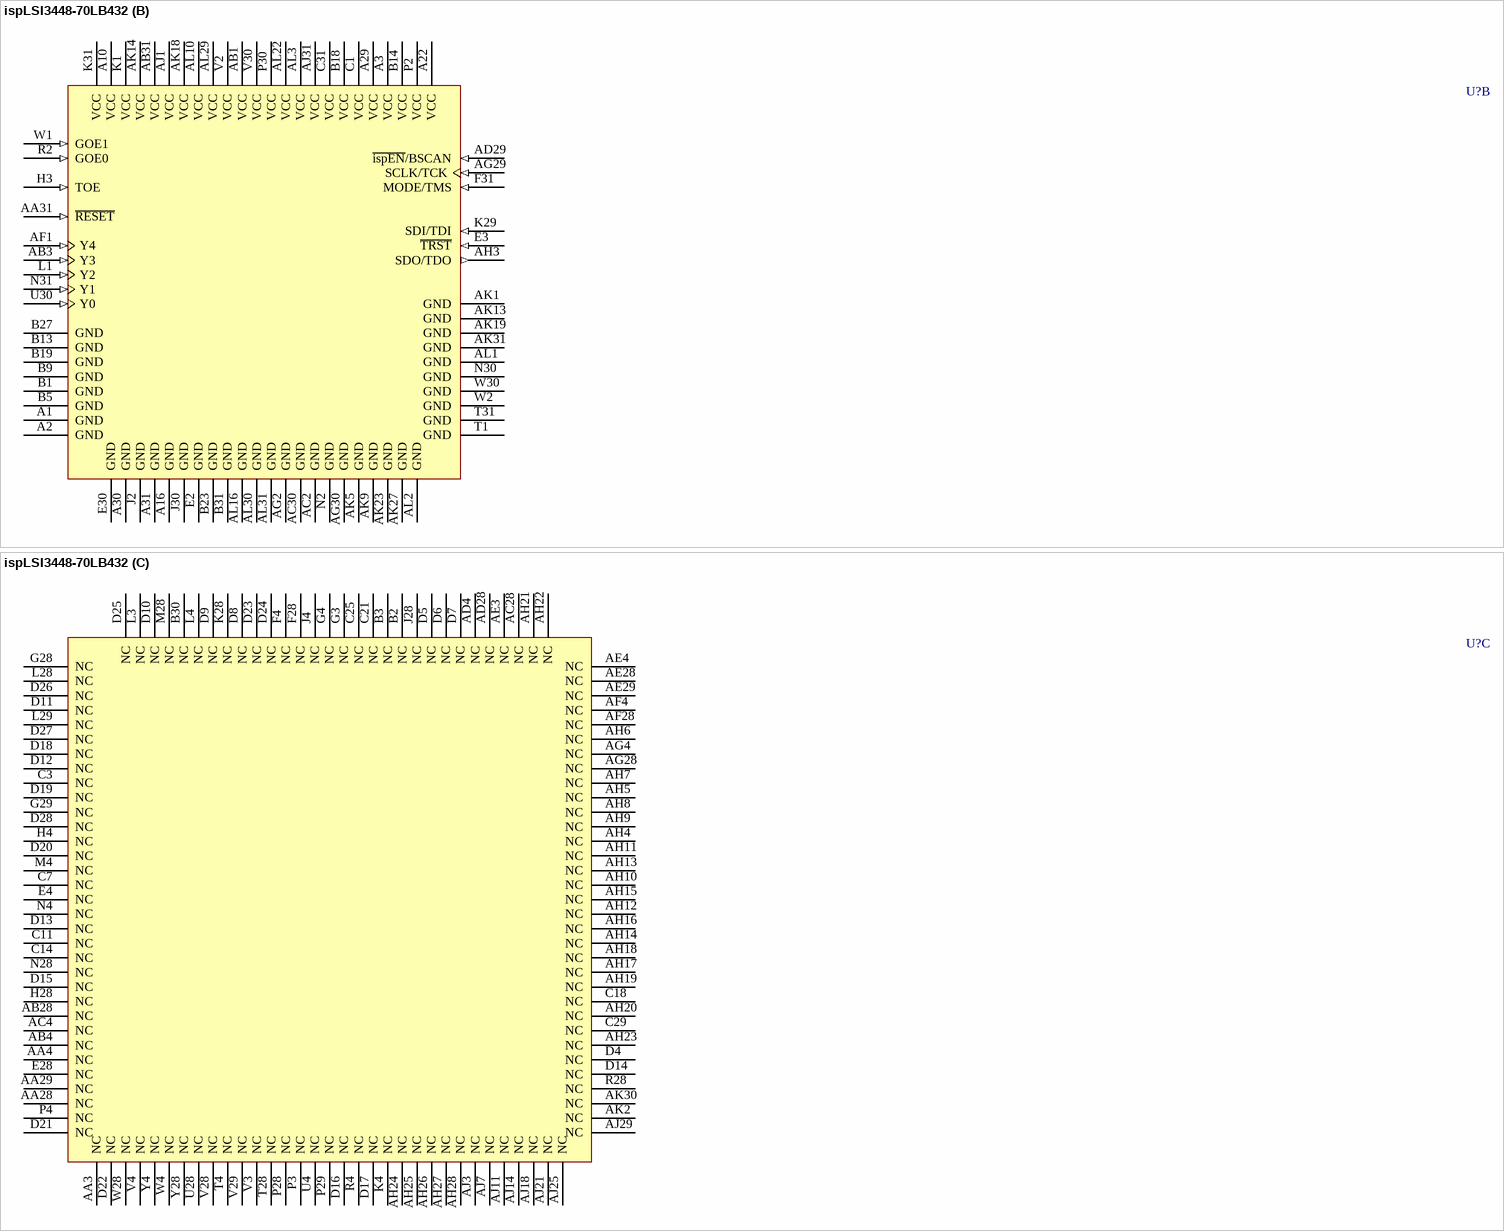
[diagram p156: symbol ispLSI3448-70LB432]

## ispLSI3448-70LB432
designator U?
In-System Programmable High-Density PLD
footprint SBGA432 (BGA, 432-Leads, Body 40x40mm, Pitch 1.27mm)
3D model 3448-SBGA432 (432-Ball Super Ball Grid Array (SBGA432))
part A pins: A4 I/O141 (io), A5 I/O142 (io), A6 I/O145 (io), A7 I/O147 (io), A8 I/O150 (io), A9 I/O152 (io), A11 I/O156 (io), A12 I/O159 (io), A13 I/O161 (io), A14 I/O162 (io), A15 I/O165 (io), A17 I/O170 (io), A18 I/O171 (io), A19 I/O172 (io), A20 I/O174 (io), A21 I/O177 (io), A23 I/O181 (io), A24 I/O183 (io), A25 I/O186 (io), A26 I/O188 (io), A27 I/O191 (io), A28 I/O192 (io), AA1 I/O102 (io), AA2 I/O101 (io), AA30 I/O9 (io), AB2 I/O100 (io), AB29 I/O11 (io), AB30 I/O10 (io), AC1 I/O99 (io), AC3 I/O98 (io), AC29 I/O13 (io), AC31 I/O12 (io), AD1 I/O97 (io), AD2 I/O96 (io), AD3 I/O95 (io), AD30 I/O15 (io), AD31 I/O14 (io), AE1 I/O94 (io), AE2 I/O93 (io), AE30 I/O17 (io), AE31 I/O16 (io), AF2 I/O92 (io), AF3 I/O91 (io), AF29 I/O20 (io), AF30 I/O19 (io), AF31 I/O18 (io), AG1 I/O90 (io), AG3 I/O88 (io), AG31 I/O21 (io), AH1 I/O89 (io), AH2 I/O87 (io), AH29 I/O25 (io), AH30 I/O23 (io), AH31 I/O22 (io), AJ2 I/O86 (io), AJ4 I/O85 (io), AJ5 I/O82 (io), AJ6 I/O79 (io), AJ8 I/O74 (io), AJ9 I/O71 (io), AJ10 I/O69 (io), AJ12 I/O65 (io), AJ13 I/O62 (io), AJ15 I/O57 (io), AJ16 I/O55 (io), AJ17 I/O52 (io), AJ19 I/O49 (io), AJ20 I/O46 (io), AJ22 I/O42 (io), AJ23 I/O40 (io), AJ24 I/O37 (io), AJ26 I/O32 (io), AJ27 I/O29 (io), AJ28 I/O26 (io), AJ30 I/O24 (io), AK3 I/O84 (io), AK4 I/O83 (io), AK6 I/O78 (io), AK7 I/O76 (io), AK8 I/O73 (io), AK10 I/O68 (io), AK11 I/O67 (io), AK12 I/O64 (io), AK15 I/O58 (io), AK16 I/O56 (io), AK17 I/O53 (io), AK20 I/O47 (io), AK21 I/O44 (io), AK22 I/O43 (io), AK24 I/O38 (io), AK25 I/O35 (io), AK26 I/O33 (io), AK28 I/O28 (io), AK29 I/O27 (io), AL4 I/O81 (io), AL5 I/O80 (io), AL6 I/O77 (io), AL7 I/O75 (io), AL8 I/O72 (io), AL9 I/O70 (io), AL11 I/O66 (io), AL12 I/O63 (io), AL13 I/O61 (io), AL14 I/O60 (io), AL15 I/O59 (io), AL17 I/O54 (io), AL18 I/O51 (io), AL19 I/O50 (io), AL20 I/O48 (io), AL21 I/O45 (io), AL23 I/O41 (io), AL24 I/O39 (io), AL25 I/O36 (io), AL26 I/O34 (io), AL27 I/O31 (io), AL28 I/O30 (io), B4 I/O139 (io), B6 I/O144 (io), B7 I/O146 (io), B8 I/O149 (io), B10 I/O154 (io), B11 I/O155 (io), B12 I/O158 (io), B15 I/O164 (io), B16 I/O167 (io), B17 I/O169 (io), B20 I/O175 (io), B21 I/O178 (io), B22 I/O179 (io), B24 I/O184 (io), B25 I/O187 (io), B26 I/O189 (io), B28 I/O194 (io), B29 I/O195 (io), C2 I/O136 (io), C4 I/O138 (io), C5 I/O140 (io), C6 I/O143 (io), C8 I/O148 (io), C9 I/O151 (io), C10 I/O153 (io), C12 I/O157 (io), C13 I/O160 (io), C15 I/O163 (io), C16 I/O166 (io), C17 I/O168 (io), C19 I/O173 (io), C20 I/O176 (io), C22 I/O180 (io), C23 I/O182 (io), C24 I/O185 (io), C26 I/O190 (io), C27 I/O193 (io), C28 I/O196 (io), C30 I/O198 (io), D1 I/O134 (io), D2 I/O135 (io), D3 I/O137 (io), D29 I/O197 (io), D30 I/O199 (io), D31 I/O201 (io), E1 I/O133 (io), E29 I/O200 (io), E31 I/O202 (io), F1 I/O130 (io), F2 I/O131 (io), F3 I/O132 (io), F29 I/O203 (io), F30 I/O204 (io), G1 I/O128 (io), G2 I/O129 (io), G30 I/O205 (io), G31 I/O206 (io), H1 I/O126 (io), H2 I/O127 (io), H29 I/O207 (io), H30 I/O208 (io), H31 I/O209 (io), J1 I/O124 (io), J3 I/O125 (io), J29 I/O210 (io), J31 I/O211 (io), K2 I/O122 (io), K3 I/O123 (io), K30 I/O212 (io), L2 I/O121 (io), L30 I/O213 (io), L31 I/O214 (io), M1 I/O118 (io), M2 I/O119 (io), M3 I/O120 (io), M29 I/O215 (io), M30 I/O216 (io), M31 I/O217 (io), N1 I/O116 (io), N3 I/O117 (io), N29 I/O218 (io), P1 I/O115 (io), P31 I/O219 (io), R1 I/O114 (io), R3 I/O113 (io), R29 I/O220 (io), R30 I/O221 (io), R31 I/O222 (io), T2 I/O112 (io), T3 I/O111 (io), T29 I/O223 (io), T30 I/O0 (io), U1 I/O110 (io), U2 I/O109 (io), U3 I/O108 (io), U29 I/O1 (io), U31 I/O2 (io), V1 I/O107 (io), V31 I/O3 (io), W3 I/O106 (io), W29 I/O5 (io), W31 I/O4 (io), Y1 I/O105 (io), Y2 I/O104 (io), Y3 I/O103 (io), Y29 I/O8 (io), Y30 I/O7 (io), Y31 I/O6 (io)
part B pins: A1 GND (power), A2 GND (power), A3 VCC (power), A10 VCC (power), A16 GND (power), A22 VCC (power), A29 VCC (power), A30 GND (power), A31 GND (power), AA31 ~{RESET} (in), AB1 VCC (power), AB3 Y3 (in), AB31 VCC (power), AC2 GND (power), AC30 GND (power), AD29 ~{ispEN}/BSCAN (in), AF1 Y4 (in), AG2 GND (power), AG29 SCLK/TCK (in), AG30 GND (power), AH3 SDO/TDO (out), AJ1 VCC (power), AJ31 VCC (power), AK1 GND (power), AK5 GND (power), AK9 GND (power), AK13 GND (power), AK14 VCC (power), AK18 VCC (power), AK19 GND (power), AK23 GND (power), AK27 GND (power), AK31 GND (power), AL1 GND (power), AL2 GND (power), AL3 VCC (power), AL10 VCC (power), AL16 GND (power), AL22 VCC (power), AL29 VCC (power), AL30 GND (power), AL31 GND (power), B1 GND (power), B5 GND (power), B9 GND (power), B13 GND (power), B14 VCC (power), B18 VCC (power), B19 GND (power), B23 GND (power), B27 GND (power), B31 GND (power), C1 VCC (power), C31 VCC (power), E2 GND (power), E3 ~{TRST} (in), E30 GND (power), F31 MODE/TMS (in), H3 TOE (in), J2 GND (power), J30 GND (power), K1 VCC (power), K29 SDI/TDI (in), K31 VCC (power), L1 Y2 (in), N2 GND (power), N30 GND (power), N31 Y1 (in), P2 VCC (power), P30 VCC (power), R2 GOE0 (in), T1 GND (power), T31 GND (power), U30 Y0 (in), V2 VCC (power), V30 VCC (power), W1 GOE1 (in), W2 GND (power), W30 GND (power)
part C pins: AA3 NC, AA4 NC, AA28 NC, AA29 NC, AB4 NC, AB28 NC, AC4 NC, AC28 NC, AD4 NC, AD28 NC, AE3 NC, AE4 NC, AE28 NC, AE29 NC, AF4 NC, AF28 NC, AG4 NC, AG28 NC, AH4 NC, AH5 NC, AH6 NC, AH7 NC, AH8 NC, AH9 NC, AH10 NC, AH11 NC, AH12 NC, AH13 NC, AH14 NC, AH15 NC, AH16 NC, AH17 NC, AH18 NC, AH19 NC, AH20 NC, AH21 NC, AH22 NC, AH23 NC, AH24 NC, AH25 NC, AH26 NC, AH27 NC, AH28 NC, AJ3 NC, AJ7 NC, AJ11 NC, AJ14 NC, AJ18 NC, AJ21 NC, AJ25 NC, AJ29 NC, AK2 NC, AK30 NC, B2 NC, B3 NC, B30 NC, C3 NC, C7 NC, C11 NC, C14 NC, C18 NC, C21 NC, C25 NC, C29 NC, D4 NC, D5 NC, D6 NC, D7 NC, D8 NC, D9 NC, D10 NC, D11 NC, D12 NC, D13 NC, D14 NC, D15 NC, D16 NC, D17 NC, D18 NC, D19 NC, D20 NC, D21 NC, D22 NC, D23 NC, D24 NC, D25 NC, D26 NC, D27 NC, D28 NC, E4 NC, E28 NC, F4 NC, F28 NC, G3 NC, G4 NC, G28 NC, G29 NC, H4 NC, H28 NC, J4 NC, J28 NC, K4 NC, K28 NC, L3 NC, L4 NC, L28 NC, L29 NC, M4 NC, M28 NC, N4 NC, N28 NC, P3 NC, P4 NC, P28 NC, P29 NC, R4 NC, R28 NC, T4 NC, T28 NC, U4 NC, U28 NC, V3 NC, V4 NC, V28 NC, V29 NC, W4 NC, W28 NC, Y4 NC, Y28 NC

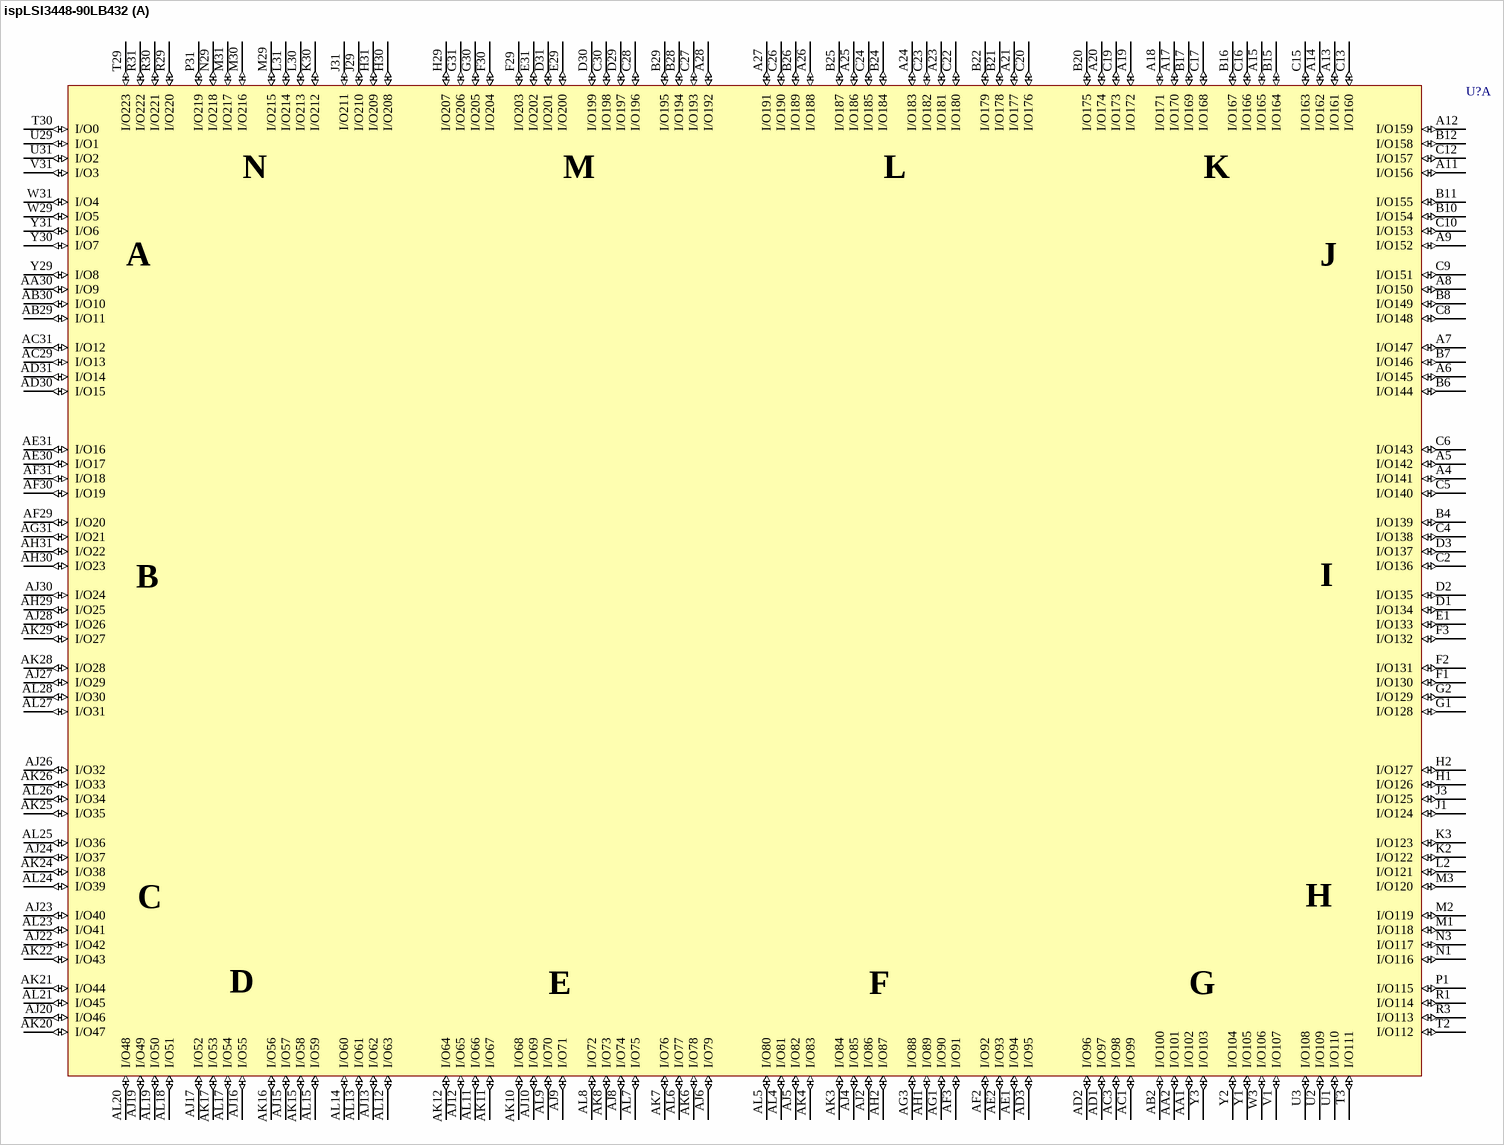
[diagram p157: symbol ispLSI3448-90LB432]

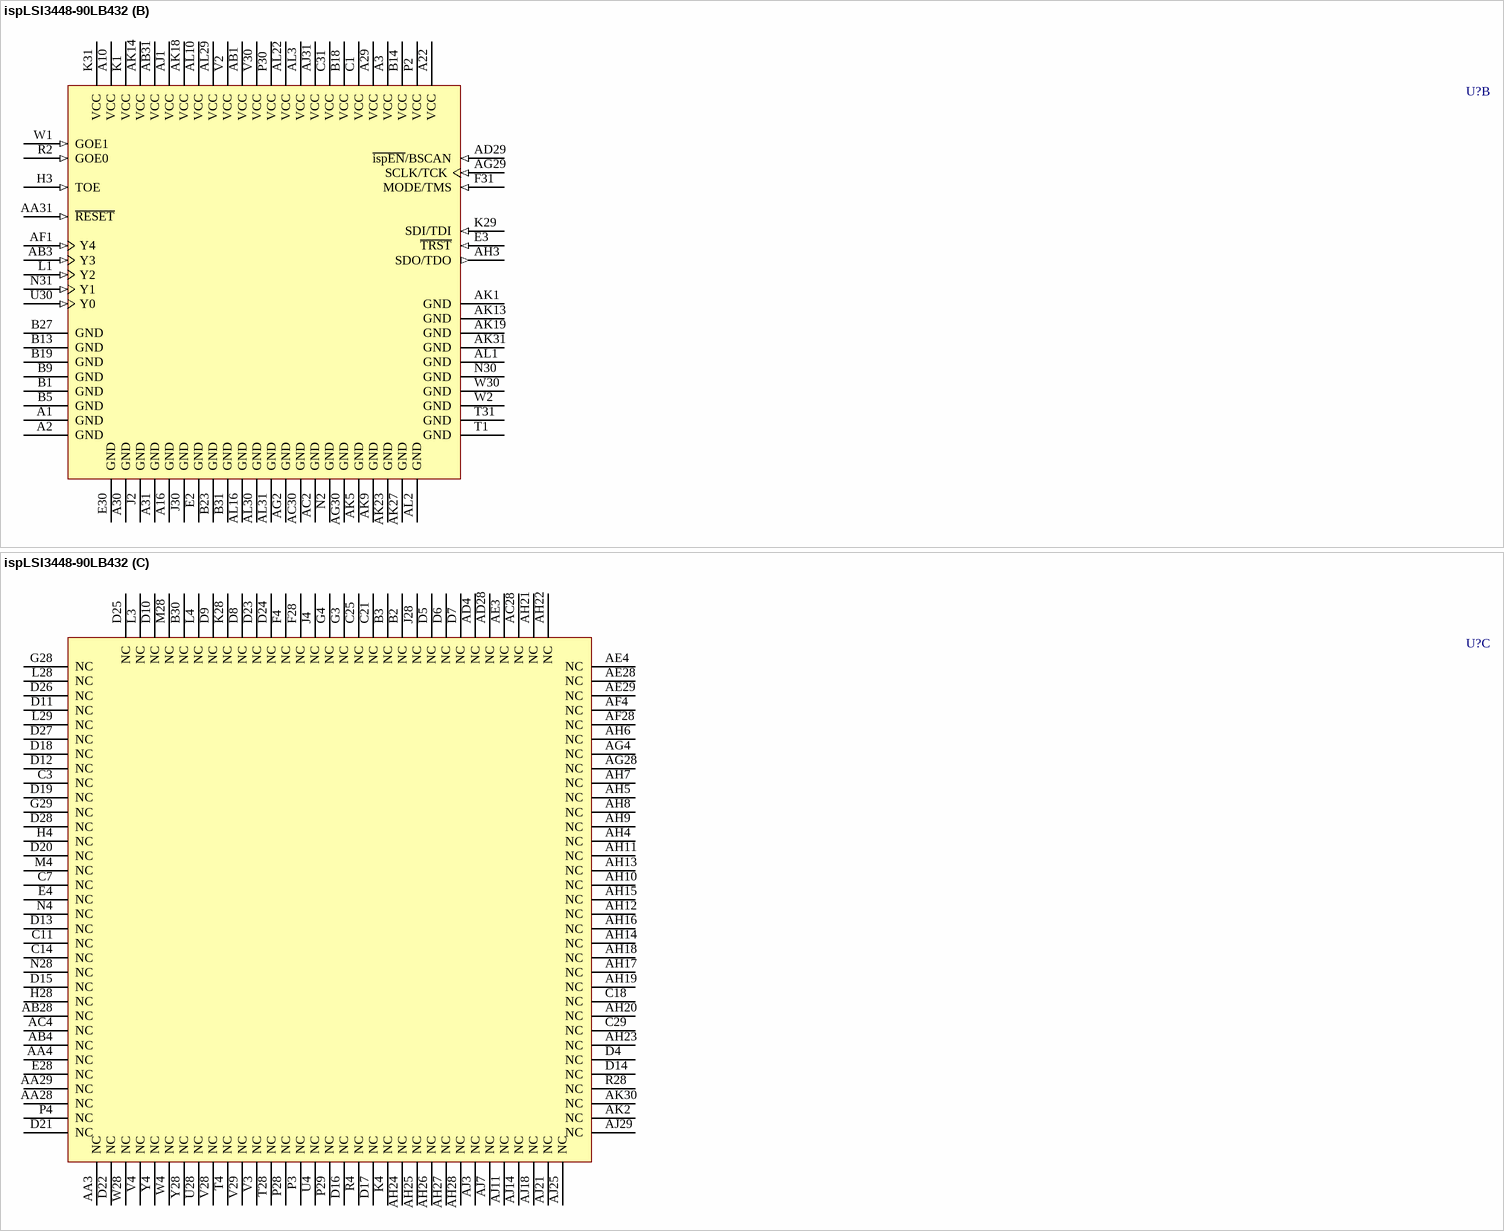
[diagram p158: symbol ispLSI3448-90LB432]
